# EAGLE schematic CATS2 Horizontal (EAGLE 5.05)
MFG: Bourns; PN: APXE160ARA390ME61G; SOCKET_MFG: Mill-Max Mfg

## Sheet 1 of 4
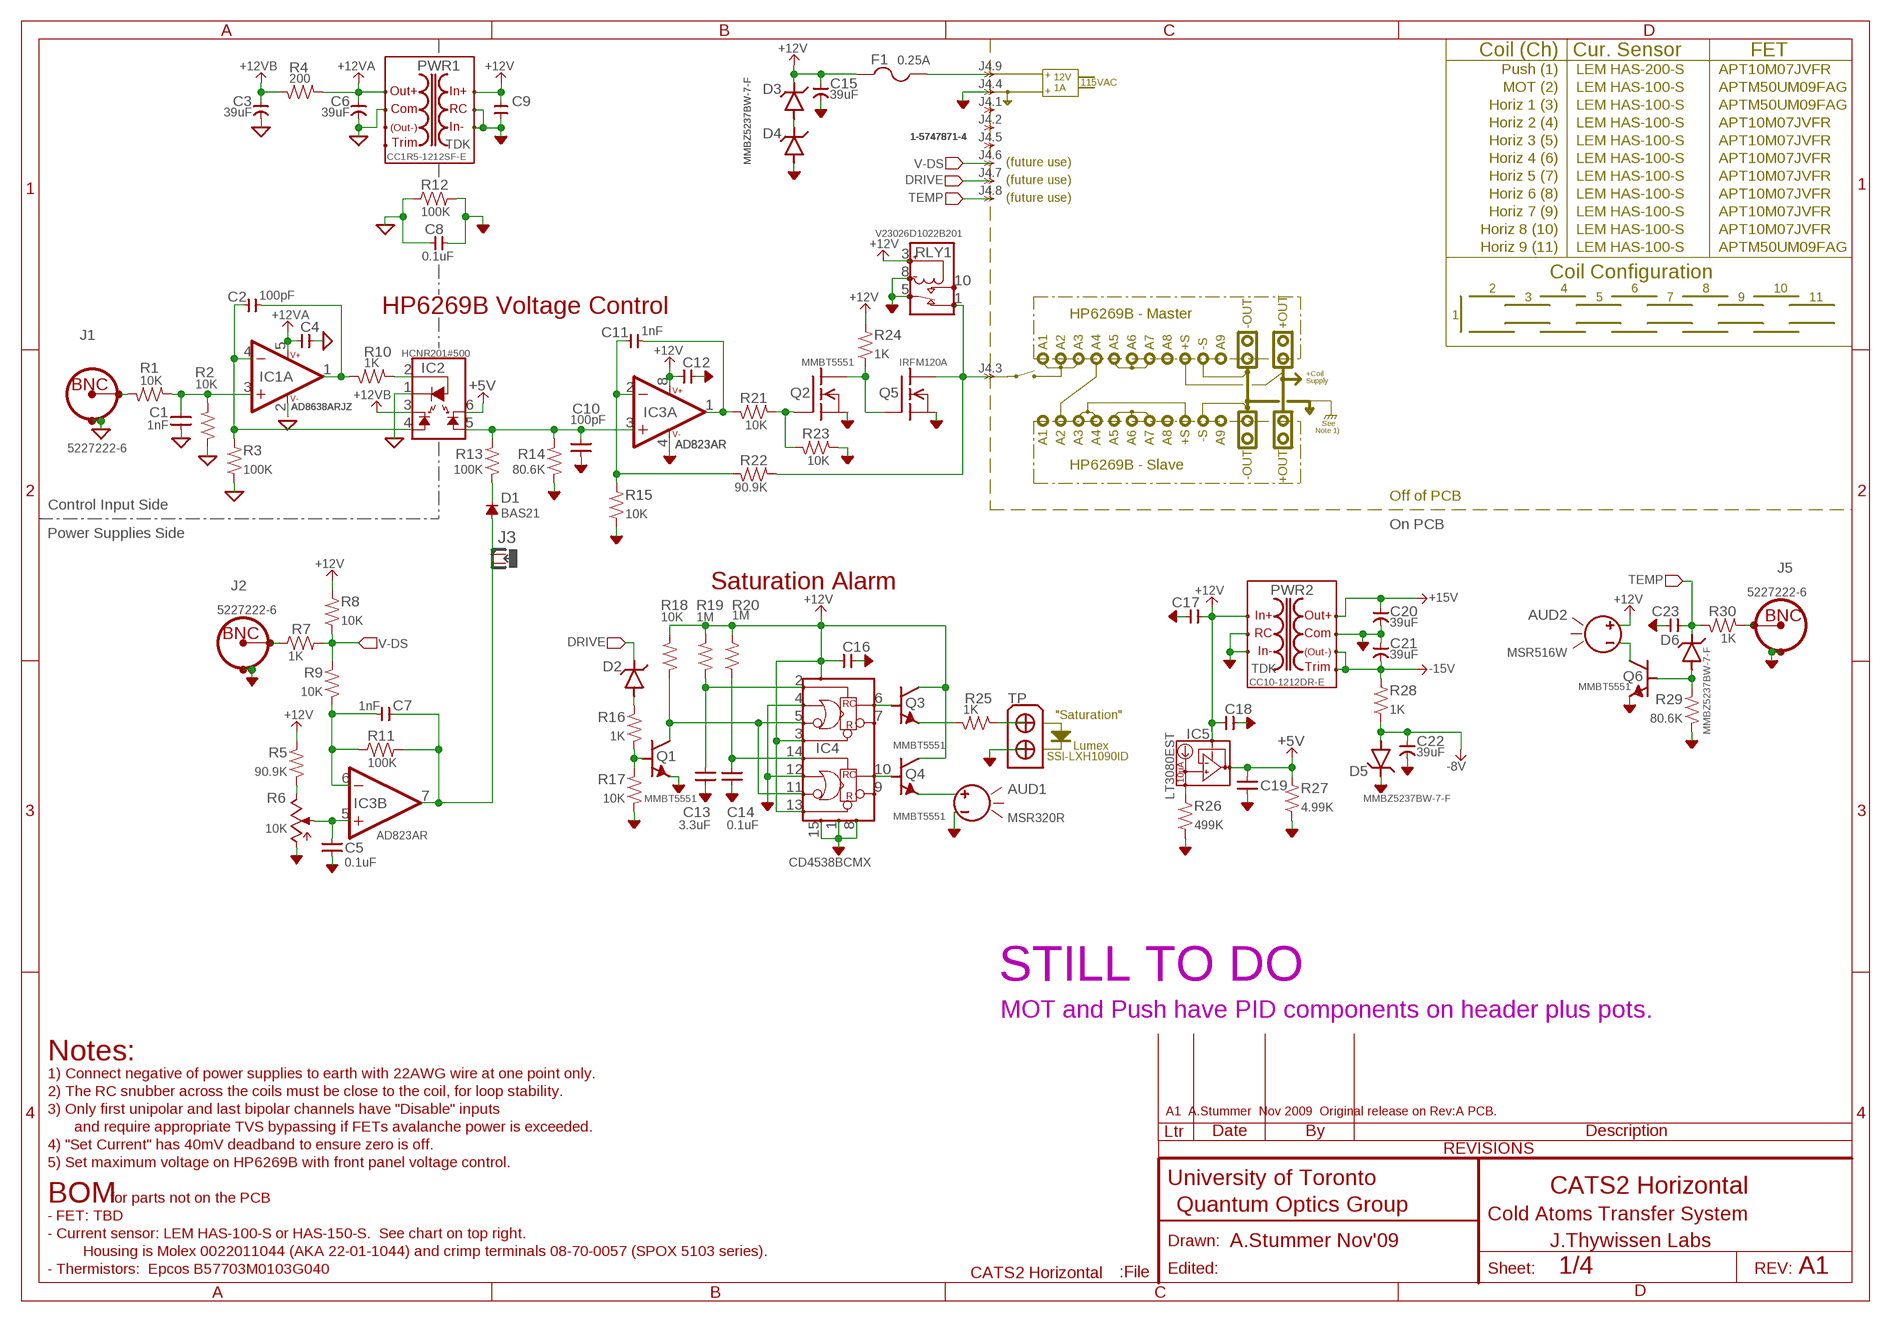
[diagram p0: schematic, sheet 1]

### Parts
AUD1  MSR320R  AUDIO_DEVICE1-MALLORY_MSR  [MALLORY_MSR]
AUD2  MSR516W  AUDIO_DEVICE1-MALLORY_MSR  [MALLORY_MSR]
C1  1nF  CAP-V-0805  [2012(0805)]
C2  100pF  CAP-H-0805  [2012(0805)]
C3  39uF  CAP-POL--NIPPONCHEM_E61  [CAP:NIPPONCHEM_E61]
C4  0.1uF  CAP-H-0805  [2012(0805)]
C5  0.1uF  CAP-V-0805  [2012(0805)]
C6  39uF  CAP-POL--NIPPONCHEM_E61  [CAP:NIPPONCHEM_E61]
C7  1nF  CAP-H-0805  [2012(0805)]
C8  0.1uF  CAP-H-0805  [2012(0805)]
C9  0.1uF  CAP-H-0805  [2012(0805)]
C10  100pF  CAP-V-0805  [2012(0805)]
C11  1nF  CAP-H-0805  [2012(0805)]
C12  0.1uF  CAP-H-0805  [2012(0805)]
C13  3.3uF  CAP-V-0805  [2012(0805)]
C14  0.1uF  CAP-V-0805  [2012(0805)]
C15  39uF  CAP-POL--NIPPONCHEM_E61  [CAP:NIPPONCHEM_E61]
C16  0.1uF  CAP-H-0805  [2012(0805)]
C17  0.1uF  CAP-H-0805  [2012(0805)]
C18  0.1uF  CAP-H-0805  [2012(0805)]
C19  0.1uF  CAP-V-0805  [2012(0805)]
C20  39uF  CAP-POL--NIPPONCHEM_E61  [CAP:NIPPONCHEM_E61]
C21  39uF  CAP-POL--NIPPONCHEM_E61  [CAP:NIPPONCHEM_E61]
C22  39uF  CAP-POL--NIPPONCHEM_E61  [CAP:NIPPONCHEM_E61]
C23  0.1uF  CAP-H-0805  [2012(0805)]
D1  BAS21  DIODE,GENERIC-SOT23  [SOT23]
D2  MMBZ5237BW-7-F  ZENER-SOT23  [SOT23]
D3  MMBZ5237BW-7-F  ZENER-SOT23  [SOT23]
D4  MMBZ5237BW-7-F  ZENER-SOT23  [SOT23]
D5  MMBZ5237BW-7-F  ZENER-SOT23  [SOT23]
D6  MMBZ5237BW-7-F  ZENER-SOT23  [SOT23]
F1  0.25A  FUSE-5X20-4  [FUSE]
IC1  AD8638ARJZ  OPAMP-SOT23-5  [SOT23-5]
IC2  HCNR201#500  OPTO:LINEAR-TYPE1AVAGO#300  [SMD:AVAGO#300(8PIN)]
IC3  AD823AR  OPAMP:AD8___(DUAL)-SOIC-8  [SOIC-8]
IC4  CD4538BCMX  LOGIC,MONOSTABLE,DUAL:MC74HC4538A-SOIC16  [SOIC-16]
IC5  LT3080EST  REGULATOR:LT3080(3PIN,LDO,I-SET)-SOT223  [SOT223(C)]
J1  5227222-6  CONN-BNC-TYPE1VERT  [CONN-BNC-AMP-TYPE1VERT]
J2  5227222-6  CONN-BNC-TYPE1VERT  [CONN-BNC-AMP-TYPE1VERT]
J3  JUMPER-1X2  [JUMPER-1X2]
J4  1-5747871-4  CONN-DB9-TYPE2-AMP_5747XXX  [CONN-DB9-H/V1]
J5  5227222-6  CONN-BNC-TYPE1VERT  [CONN-BNC-AMP-TYPE1VERT]
PWR1  CC1R5-1212SF-E  DC-DC:CCP-__-E(TDK1.5-25W)-CC1R5-R-E  [DC-DC:CC1R5-XXXXX-R-E(TDK/LAMBDA)]
PWR2  CC10-1212DR-E  DC-DC:CCP-__-E(TDK1.5-25W)-CC10-R-E  [DC-DC:CC10-XXXXX-R-E(TDK/LAMBDA)]
Q1  MMBT5551  BJT-NPN-SOT23  [SOT23]
Q2  MMBT5551  MOSFET-N-SOT23(2N7000/2)  [SOT23]
Q3  MMBT5551  BJT-NPN-SOT23  [SOT23]
Q4  MMBT5551  BJT-NPN-SOT23  [SOT23]
Q5  IRFM120A  MOSFET-N-SOT223(C)  [SOT223(C)]
Q6  MMBT5551  BJT-NPN-SOT23  [SOT23]
R1  10K  R-H-0805  [2012(0805)]
R2  10K  R-V-0805  [2012(0805)]
R3  100K  R-V-0805  [2012(0805)]
R4  200  R-H-0805  [2012(0805)]
R5  90.9K  R-V-0805  [2012(0805)]
R6  10K  POT-BOURNS_3361P  [BOURNS_3361P]
R7  1K  R-H-0805  [2012(0805)]
R8  10K  R-V-0805  [2012(0805)]
R9  10K  R-V-0805  [2012(0805)]
R10  1K  R-H-0805  [2012(0805)]
R11  100K  R-H-0805  [2012(0805)]
R12  100K  R-H-0805  [2012(0805)]
R13  100K  R-V-0805  [2012(0805)]
R14  80.6K  R-V-0805  [2012(0805)]
R15  10K  R-V-0805  [2012(0805)]
R16  1K  R-V-0805  [2012(0805)]
R17  10K  R-V-0805  [2012(0805)]
R18  10K  R-V-0805  [2012(0805)]
R19  1M  R-V-0805  [2012(0805)]
R20  1M  R-V-0805  [2012(0805)]
R21  10K  R-H-0805  [2012(0805)]
R22  90.9K  R-H-0805  [2012(0805)]
R23  10K  R-H-0805  [2012(0805)]
R24  1K  R-V-0805  [2012(0805)]
R25  1K  R-H-0805  [2012(0805)]
R26  499K  R-V-0805  [2012(0805)]
R27  4.99K  R-V-0805  [2012(0805)]
R28  1K  R-V-0805  [2012(0805)]
R29  80.6K  R-V-0805  [2012(0805)]
R30  1K  R-H-0805  [2012(0805)]
RLY1  V23026D1022B201  RELAY:SPDT-TYCO_V23026(SMT)  [RELAY:SPDT-TYCO_V23026]
TP  CONN-TP2-1X2  [JUMPER-1X2]

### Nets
+5V: C19.2 IC2.6(VCC2) IC5.2(OUT) R27.2 ; also sheet 2,3,4
+12V [Power]: AUD2.+ C9.1 C12.1 C15.POS C16.1 C17.1 C18.1 D3.3(C) F1.1A IC3.8(PWR:V++) IC4.3(RST1) IC4.13(RST2) IC4.16(VCC) IC5.3(IN) PWR1.+VIN(+IN) PWR2.+VIN(+IN) Q3.3(C) Q4.3(C) R5.2 R8.2 R18.2 R19.2 R20.2 R24.2 RLY1.3(COIL+) ; also sheet 2,3,4
+12VA [Power]: C4.1 C6.POS IC1.5(B:V++) PWR1.+VOUT(+OUT) R4.1 ; also sheet 2,3,4
+12VB: C3.POS IC2.3(VCC1) R4.2 ; also sheet 2,3,4
+15V [Power]: C20.POS PWR2.+VOUT(+OUT) ; also sheet 2,3,4
-8V: C22.POS D5.1(A) R28.1 ; also sheet 2,3,4
-15V [Power]: C21.NEG PWR2.-VOUT(-OUT) PWR2.TRM(TRIM) R28.2 ; also sheet 2,3,4
AGND: AUD1.- C5.1 C8.2 C9.2 C10.1 C12.2 C13.1 C14.1 C15.NEG C16.2 C17.2 C18.2 C19.1 C20.NEG C21.POS C22.NEG C23.2 D4.1(A) D5.3(C) IC3.4(PWR:V-) IC4.1(COM1) IC4.4(A1) IC4.8(COM2) IC4.12(A2) IC4.15(COM3) J2.SHIELD1 J2.SHIELD2 J4.4 J5.SHIELD1 J5.SHIELD2 PWR1.-VIN(-IN) PWR1.RC PWR2.-VIN(-IN) PWR2.COM PWR2.RC Q1.2(E) Q2.2(S) Q5.3(S) Q6.2(E) R6.CCW R12.2 R14.1 R15.1 R17.1 R23.1 R26.1 R27.1 R29.1 RLY1.5(COM) RLY1.8(COIL-) TP.2 ; also sheet 2,3,4
DRIVE: D2.3(C) J4.7 ; also sheet 2,3,4
GND: C1.1 C3.NEG C4.2 C6.NEG C8.1 IC1.2(B:V-) IC2.1(LED-) J1.SHIELD1 J1.SHIELD2 PWR1.COM R2.1 R3.1 R12.1 ; also sheet 2,3,4
N$1: Q2.1(G) R21.1 R23.2
N$2: C11.2 IC3.1(A:OUT) R21.2
N$3: Q2.3(D) Q5.1(G) R24.1
N$4: C11.1 IC3.2(A:-IN) R15.2 R22.2
N$8: J5.CONDUCTOR R30.1
N$9: D3.1(A) D4.3(C)
N$10: D2.1(A) R16.2
N$11: IC4.5(B1) IC4.11(B2) Q1.3(C) R18.1
N$12: IC4.6(Q1) Q3.1(B)
N$13: C14.2 IC4.14(RC2) R20.1
N$14: C13.2 IC4.2(RC1) R19.1
N$15: IC4.10(Q2) Q4.1(B)
N$16: AUD1.+ Q4.2(E)
N$17: R25.1 TP.1
N$18: Q3.2(E) R25.2
N$19: J2.CONDUCTOR R7.1
N$20: J4.3 Q5.2(D) R22.1 RLY1.1(NC)
N$24: Q1.1(B) R16.1 R17.2
N$29: D6.1(A) Q6.1(B) R29.2
N$30: IC5.1(SET) R26.2
N$31 [Power]: F1.2A J4.9
N$41: AUD2.- Q6.3(C)
N$48: D1.1(A) J3.1
N$49: C10.2 IC2.5(I2) IC3.3(A:+IN) R13.2 R14.2
N$50: C2.2 IC1.1(A:OUT) R10.2
N$51: IC2.2(LED+) R10.1
N$52: J1.CONDUCTOR R1.2
N$53: C1.2 IC1.3(A:+IN) R1.1 R2.2
N$54: C2.1 IC1.4(A:-IN) IC2.4(I1) R3.2
N$60: C5.2 IC3.5(B:+IN) R6.W
N$70: R5.1 R6.CW
N$72: C7.1 IC3.7(B:OUT) J3.2 R11.2
N$77: D1.3(C) R13.1
N$78: C7.2 IC3.6(B:-IN) R9.1 R11.1
TEMP: C23.1 D6.3(C) J4.8 R30.2 ; also sheet 2,3,4
V-DS: J4.6 R7.2 R8.1 R9.2 ; also sheet 2,3,4
Unconnected: IC4.7(~Q1) IC4.9(~Q2) J4.1 J4.2 J4.5 PWR1.-VOUT(-OUT) PWR1.TRM(TRIM) RLY1.10(NO)

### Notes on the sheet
- Coil (Ch) | Cur. Sensor | FET
- Push (1) | LEM HAS-200-S | APT10M07JVFR
- + | 12V
- 115VAC
- 1A | MOT (2) | LEM HAS-100-S | APTM50UM09FAG
- +
- Horiz 1 (3) | LEM HAS-100-S | APTM50UM09FAG
- Horiz 2 (4) | LEM HAS-100-S | APT10M07JVFR
- Horiz 3 (5) | LEM HAS-100-S | APT10M07JVFR
- Horiz 4 (6) | LEM HAS-100-S | APT10M07JVFR
- (future use)
- Horiz 5 (7) | LEM HAS-100-S | APT10M07JVFR
- (future use)
- (future use) | Horiz 6 (8) | LEM HAS-100-S | APT10M07JVFR
- Horiz 7 (9) | LEM HAS-100-S | APT10M07JVFR
- Horiz 8 (10) | LEM HAS-100-S | APT10M07JVFR
- Horiz 9 (11) | LEM HAS-100-S | APTM50UM09FAG
- Coil Configuration
- 2 | 4 | 6 | 8 | 10
- 3 | 5 | 7 | 9 | 11
- HP6269B Voltage Control
- HP6269B - Master | 1
- -OUT | +OUT
- A1 | A2 | A3 | A4 | A5 | A6 | A7 | A8 | +S | -S | A9
- +Coil
- Supply
- See
- A1 | A2 | A3 | A4 | A5 | A6 | A7 | A8 | +S | -S | A9
- Note 1)
- -OUT | +OUT
- HP6269B - Slave
- Off of PCB
- Control Input Side
- On PCB
- Power Supplies Side
- Saturation Alarm
- "Saturation"
- Lumex
- SSI-LXH1090ID
- STILL TO DO
- MOT and Push have PID components on header plus pots.
- Notes:
- 1) Connect negative of power supplies to earth with 22AWG wire at one point only.
- 2) The RC snubber across the coils must be close to the coil, for loop stability.
- 3) Only first unipolar and last bipolar channels have "Disable" inputs | A1  A.Stummer  Nov 2009  Original release on Rev:A PCB.
- and require appropriate TVS bypassing if FETs avalanche power is exceeded.
- 4) "Set Current" has 40mV deadband to ensure zero is off.
- 5) Set maximum voltage on HP6269B with front panel voltage control.
- CATS2 Horizontal
- BOM | for parts not on the PCB
- - FET: TBD | Cold Atoms Transfer System
- - Current sensor: LEM HAS-100-S or HAS-150-S.  See chart on top right.
- A.Stummer Nov'09 | J.Thywissen Labs
- Housing is Molex 0022011044 (AKA 22-01-1044) and crimp terminals 08-70-0057 (SPOX 5103 series).
- - Thermistors:  Epcos B57703M0103G040 | A1

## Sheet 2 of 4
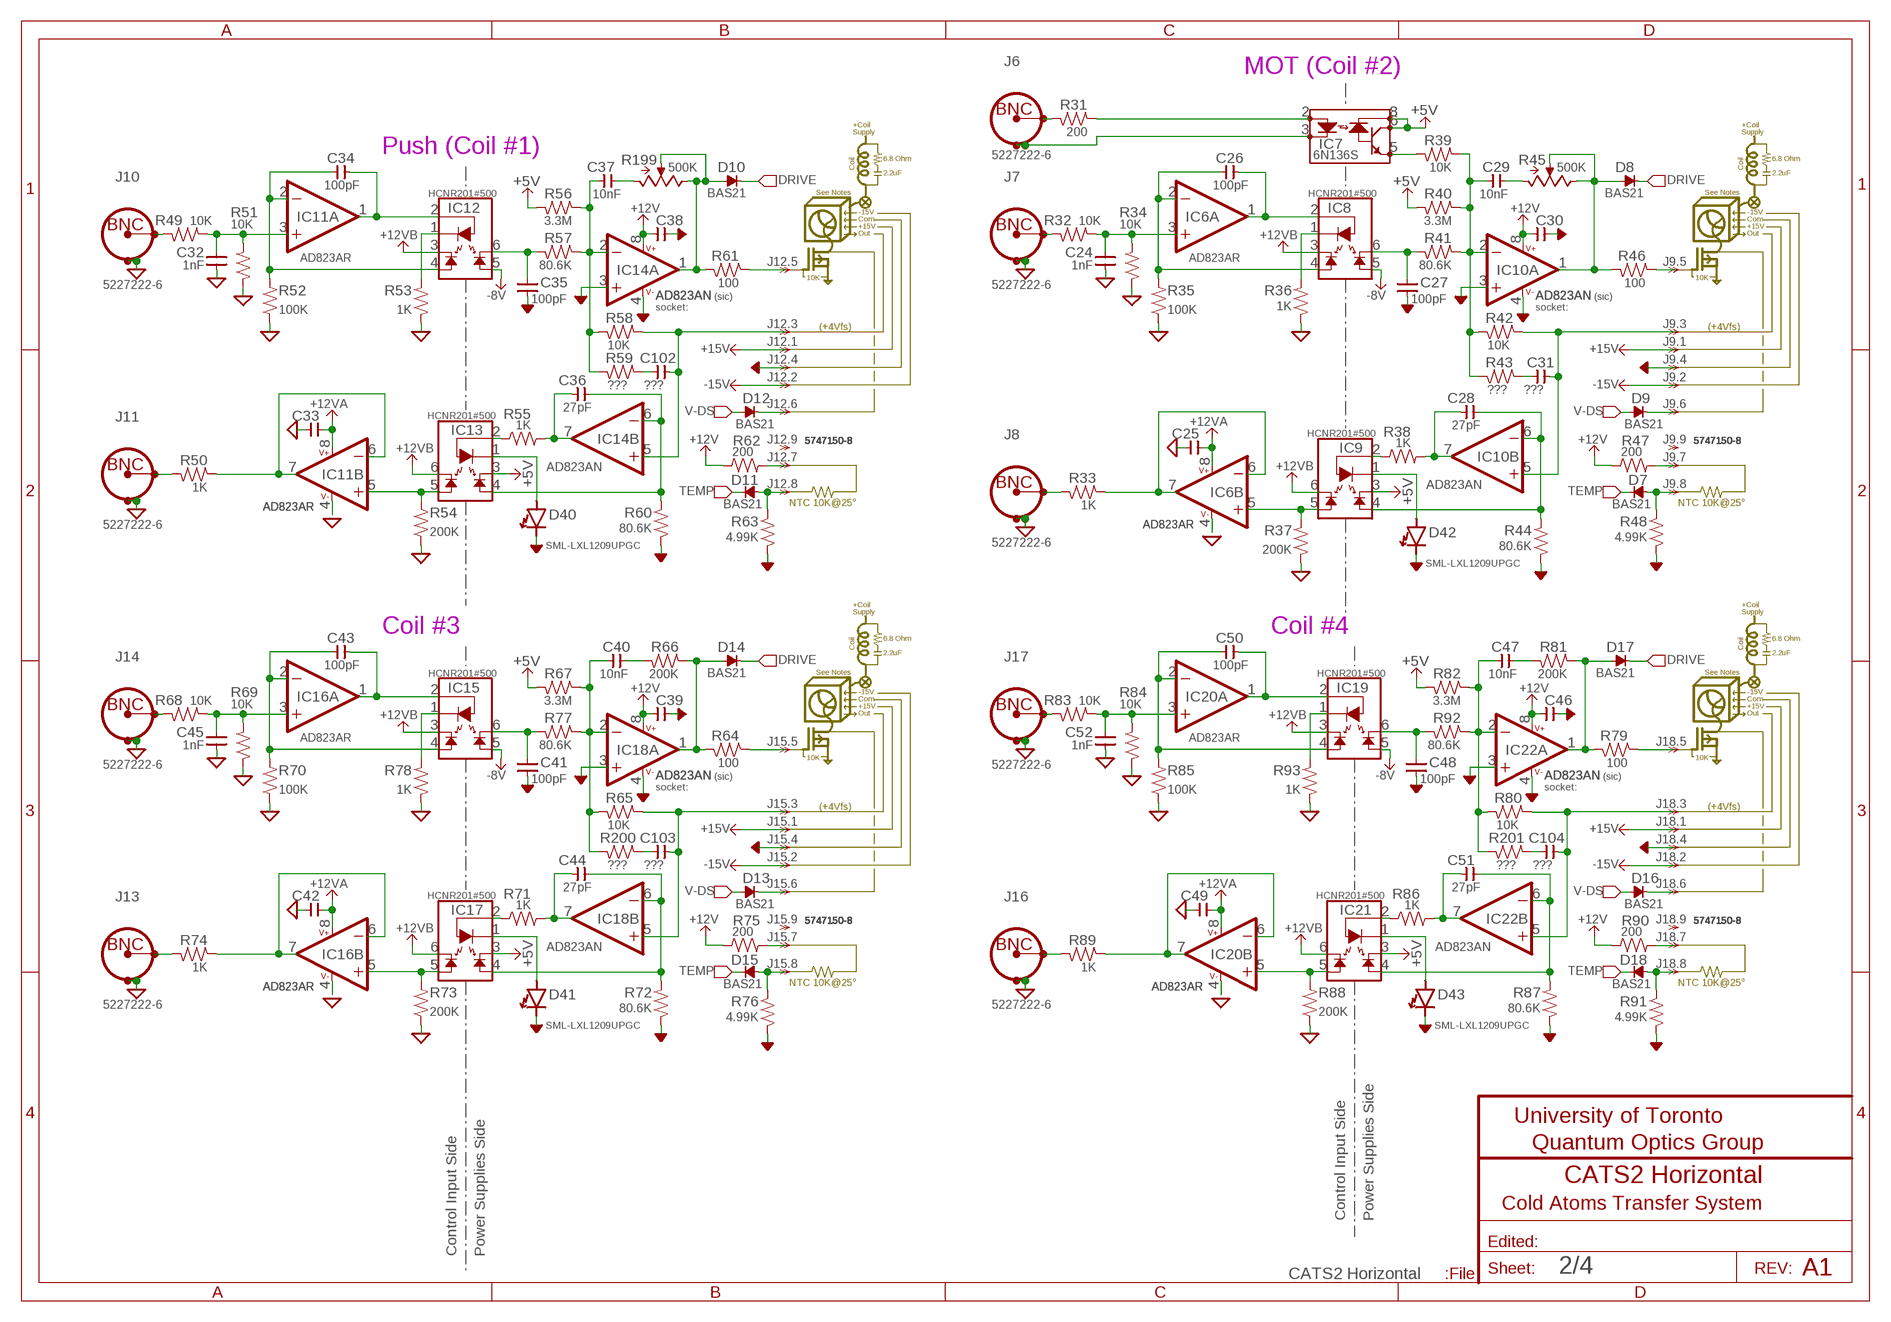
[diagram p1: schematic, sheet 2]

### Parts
C24  1nF  CAP-V-0805  [2012(0805)]
C25  0.1uF  CAP-H-0805  [2012(0805)]
C26  100pF  CAP-H-0805  [2012(0805)]
C27  100pF  CAP-V-0805  [2012(0805)]
C28  27pF  CAP-H-0805  [2012(0805)]
C29  10nF  CAP-H-0805  [2012(0805)]
C30  0.1uF  CAP-H-0805  [2012(0805)]
C31  ???  CAP-H-0805  [2012(0805)]
C32  1nF  CAP-V-0805  [2012(0805)]
C33  0.1uF  CAP-H-0805  [2012(0805)]
C34  100pF  CAP-H-0805  [2012(0805)]
C35  100pF  CAP-V-0805  [2012(0805)]
C36  27pF  CAP-H-0805  [2012(0805)]
C37  10nF  CAP-H-0805  [2012(0805)]
C38  0.1uF  CAP-H-0805  [2012(0805)]
C39  0.1uF  CAP-H-0805  [2012(0805)]
C40  10nF  CAP-H-0805  [2012(0805)]
C41  100pF  CAP-V-0805  [2012(0805)]
C42  0.1uF  CAP-H-0805  [2012(0805)]
C43  100pF  CAP-H-0805  [2012(0805)]
C44  27pF  CAP-H-0805  [2012(0805)]
C45  1nF  CAP-V-0805  [2012(0805)]
C46  0.1uF  CAP-H-0805  [2012(0805)]
C47  10nF  CAP-H-0805  [2012(0805)]
C48  100pF  CAP-V-0805  [2012(0805)]
C49  0.1uF  CAP-H-0805  [2012(0805)]
C50  100pF  CAP-H-0805  [2012(0805)]
C51  27pF  CAP-H-0805  [2012(0805)]
C52  1nF  CAP-V-0805  [2012(0805)]
C102  ???  CAP-H-0805  [2012(0805)]
C103  ???  CAP-H-0805  [2012(0805)]
C104  ???  CAP-H-0805  [2012(0805)]
D7  BAS21  DIODE,GENERIC-SOT23  [SOT23]
D8  BAS21  DIODE,GENERIC-SOT23  [SOT23]
D9  BAS21  DIODE,GENERIC-SOT23  [SOT23]
D10  BAS21  DIODE,GENERIC-SOT23  [SOT23]
D11  BAS21  DIODE,GENERIC-SOT23  [SOT23]
D12  BAS21  DIODE,GENERIC-SOT23  [SOT23]
D13  BAS21  DIODE,GENERIC-SOT23  [SOT23]
D14  BAS21  DIODE,GENERIC-SOT23  [SOT23]
D15  BAS21  DIODE,GENERIC-SOT23  [SOT23]
D16  BAS21  DIODE,GENERIC-SOT23  [SOT23]
D17  BAS21  DIODE,GENERIC-SOT23  [SOT23]
D18  BAS21  DIODE,GENERIC-SOT23  [SOT23]
D40  SML-LXL1209UPGC  LED-1209  [1209]
D41  SML-LXL1209UPGC  LED-1209  [1209]
D42  SML-LXL1209UPGC  LED-1209  [1209]
D43  SML-LXL1209UPGC  LED-1209  [1209]
IC6  AD823AR  OPAMP:AD8___(DUAL)-SOIC-8  [SOIC-8]
IC7  6N136S  OPTO:6N136-S  [SMD:6N13X(8PIN)]
IC8  HCNR201#500  OPTO:LINEAR-TYPE1AVAGO#300  [SMD:AVAGO#300(8PIN)]
IC9  HCNR201#500  OPTO:LINEAR-TYPE1AVAGO#300  [SMD:AVAGO#300(8PIN)]
IC10  AD823AN  OPAMP:AD8___(DUAL)-DIP8  [DIL08]
IC11  AD823AR  OPAMP:AD8___(DUAL)-SOIC-8  [SOIC-8]
IC12  HCNR201#500  OPTO:LINEAR-TYPE1AVAGO#300  [SMD:AVAGO#300(8PIN)]
IC13  HCNR201#500  OPTO:LINEAR-TYPE1AVAGO#300  [SMD:AVAGO#300(8PIN)]
IC14  AD823AN  OPAMP:AD8___(DUAL)-DIP8  [DIL08]
IC15  HCNR201#500  OPTO:LINEAR-TYPE1AVAGO#300  [SMD:AVAGO#300(8PIN)]
IC16  AD823AR  OPAMP:AD8___(DUAL)-SOIC-8  [SOIC-8]
IC17  HCNR201#500  OPTO:LINEAR-TYPE1AVAGO#300  [SMD:AVAGO#300(8PIN)]
IC18  AD823AN  OPAMP:AD8___(DUAL)-DIP8  [DIL08]
IC19  HCNR201#500  OPTO:LINEAR-TYPE1AVAGO#300  [SMD:AVAGO#300(8PIN)]
IC20  AD823AR  OPAMP:AD8___(DUAL)-SOIC-8  [SOIC-8]
IC21  HCNR201#500  OPTO:LINEAR-TYPE1AVAGO#300  [SMD:AVAGO#300(8PIN)]
IC22  AD823AN  OPAMP:AD8___(DUAL)-DIP8  [DIL08]
J6  5227222-6  CONN-BNC-TYPE1VERT  [CONN-BNC-AMP-TYPE1VERT]
J7  5227222-6  CONN-BNC-TYPE1VERT  [CONN-BNC-AMP-TYPE1VERT]
J8  5227222-6  CONN-BNC-TYPE1VERT  [CONN-BNC-AMP-TYPE1VERT]
J9  5747150-8  CONN-DB9-TYPE2-AMP_5747XXX  [CONN-DB9-H/V1]
J10  5227222-6  CONN-BNC-TYPE1VERT  [CONN-BNC-AMP-TYPE1VERT]
J11  5227222-6  CONN-BNC-TYPE1VERT  [CONN-BNC-AMP-TYPE1VERT]
J12  5747150-8  CONN-DB9-TYPE2-AMP_5747XXX  [CONN-DB9-H/V1]
J13  5227222-6  CONN-BNC-TYPE1VERT  [CONN-BNC-AMP-TYPE1VERT]
J14  5227222-6  CONN-BNC-TYPE1VERT  [CONN-BNC-AMP-TYPE1VERT]
J15  5747150-8  CONN-DB9-TYPE2-AMP_5747XXX  [CONN-DB9-H/V1]
J16  5227222-6  CONN-BNC-TYPE1VERT  [CONN-BNC-AMP-TYPE1VERT]
J17  5227222-6  CONN-BNC-TYPE1VERT  [CONN-BNC-AMP-TYPE1VERT]
J18  5747150-8  CONN-DB9-TYPE2-AMP_5747XXX  [CONN-DB9-H/V1]
R31  200  R-H-0805  [2012(0805)]
R32  10K  R-H-0805  [2012(0805)]
R33  1K  R-H-0805  [2012(0805)]
R34  10K  R-V-0805  [2012(0805)]
R35  100K  R-V-0805  [2012(0805)]
R36  1K  R-V-0805  [2012(0805)]
R37  200K  R-V-0805  [2012(0805)]
R38  1K  R-H-0805  [2012(0805)]
R39  10K  R-H-0805  [2012(0805)]
R40  3.3M  R-H-0805  [2012(0805)]
R41  80.6K  R-H-0805  [2012(0805)]
R42  10K  R-H-0805  [2012(0805)]
R43  ???  R-H-0805  [2012(0805)]
R44  80.6K  R-V-0805  [2012(0805)]
R45  500K  POT-BOURNS_3361P  [BOURNS_3361P]
R46  100  R-H-0805  [2012(0805)]
R47  200  R-H-0805  [2012(0805)]
R48  4.99K  R-V-0805  [2012(0805)]
R49  10K  R-H-0805  [2012(0805)]
R50  1K  R-H-0805  [2012(0805)]
R51  10K  R-V-0805  [2012(0805)]
R52  100K  R-V-0805  [2012(0805)]
R53  1K  R-V-0805  [2012(0805)]
R54  200K  R-V-0805  [2012(0805)]
R55  1K  R-H-0805  [2012(0805)]
R56  3.3M  R-H-0805  [2012(0805)]
R57  80.6K  R-H-0805  [2012(0805)]
R58  10K  R-H-0805  [2012(0805)]
R59  ???  R-H-0805  [2012(0805)]
R60  80.6K  R-V-0805  [2012(0805)]
R61  100  R-H-0805  [2012(0805)]
R62  200  R-H-0805  [2012(0805)]
R63  4.99K  R-V-0805  [2012(0805)]
R64  100  R-H-0805  [2012(0805)]
R65  10K  R-H-0805  [2012(0805)]
R66  200K  R-H-0805  [2012(0805)]
R67  3.3M  R-H-0805  [2012(0805)]
R68  10K  R-H-0805  [2012(0805)]
R69  10K  R-V-0805  [2012(0805)]
R70  100K  R-V-0805  [2012(0805)]
R71  1K  R-H-0805  [2012(0805)]
R72  80.6K  R-V-0805  [2012(0805)]
R73  200K  R-V-0805  [2012(0805)]
R74  1K  R-H-0805  [2012(0805)]
R75  200  R-H-0805  [2012(0805)]
R76  4.99K  R-V-0805  [2012(0805)]
R77  80.6K  R-H-0805  [2012(0805)]
R78  1K  R-V-0805  [2012(0805)]
R79  100  R-H-0805  [2012(0805)]
R80  10K  R-H-0805  [2012(0805)]
R81  200K  R-H-0805  [2012(0805)]
R82  3.3M  R-H-0805  [2012(0805)]
R83  10K  R-H-0805  [2012(0805)]
R84  10K  R-V-0805  [2012(0805)]
R85  100K  R-V-0805  [2012(0805)]
R86  1K  R-H-0805  [2012(0805)]
R87  80.6K  R-V-0805  [2012(0805)]
R88  200K  R-V-0805  [2012(0805)]
R89  1K  R-H-0805  [2012(0805)]
R90  200  R-H-0805  [2012(0805)]
R91  4.99K  R-V-0805  [2012(0805)]
R92  80.6K  R-H-0805  [2012(0805)]
R93  1K  R-V-0805  [2012(0805)]
R199  500K  POT-BOURNS_3361P  [BOURNS_3361P]
R200  ???  R-H-0805  [2012(0805)]
R201  ???  R-H-0805  [2012(0805)]

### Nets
+5V: IC7.6(OUT) IC7.8(VDD) IC9.3(VCC1) IC13.3(VCC1) IC17.3(VCC1) IC21.3(VCC1) R40.2 R56.2 R67.2 R82.2 ; also sheet 1,3,4
+12V [Power]: C30.1 C38.1 C39.1 C46.1 IC10.8(PWR:V++) IC14.8(PWR:V++) IC18.8(PWR:V++) IC22.8(PWR:V++) R47.1 R62.1 R75.1 R90.1 ; also sheet 1,3,4
+12VA [Power]: C25.1 C33.1 C42.1 C49.1 IC6.8(PWR:V++) IC11.8(PWR:V++) IC16.8(PWR:V++) IC20.8(PWR:V++) ; also sheet 1,3,4
+12VB: IC8.3(VCC1) IC9.6(VCC2) IC12.3(VCC1) IC13.6(VCC2) IC15.3(VCC1) IC17.6(VCC2) IC19.3(VCC1) IC21.6(VCC2) ; also sheet 1,3,4
+15V [Power]: J9.1 J12.1 J15.1 J18.1 ; also sheet 1,3,4
-8V: IC8.5(I2) IC12.5(I2) IC15.5(I2) IC19.5(I2) ; also sheet 1,3,4
-15V [Power]: J9.2 J12.2 J15.2 J18.2 ; also sheet 1,3,4
AGND: C27.1 C30.2 C35.1 C38.2 C39.2 C41.1 C46.2 C48.1 D40.K(C) D41.K(C) D42.K(C) D43.K(C) IC10.3(A:+IN) IC10.4(PWR:V-) IC14.3(A:+IN) IC14.4(PWR:V-) IC18.3(A:+IN) IC18.4(PWR:V-) IC22.3(A:+IN) IC22.4(PWR:V-) J9.4 J12.4 J15.4 J18.4 R44.1 R48.1 R60.1 R63.1 R72.1 R76.1 R87.1 R91.1 ; also sheet 1,3,4
DRIVE: D8.3(C) D10.3(C) D14.3(C) D17.3(C) ; also sheet 1,3,4
GND: C24.1 C25.2 C32.1 C33.2 C42.2 C45.1 C49.2 C52.1 IC6.4(PWR:V-) IC11.4(PWR:V-) IC16.4(PWR:V-) IC20.4(PWR:V-) J7.SHIELD1 J7.SHIELD2 J8.SHIELD1 J8.SHIELD2 J10.SHIELD1 J10.SHIELD2 J11.SHIELD1 J11.SHIELD2 J13.SHIELD1 J13.SHIELD2 J14.SHIELD1 J14.SHIELD2 J16.SHIELD1 J16.SHIELD2 J17.SHIELD1 J17.SHIELD2 R34.1 R35.1 R36.1 R37.1 R51.1 R52.1 R53.1 R54.1 R69.1 R70.1 R73.1 R78.1 R84.1 R85.1 R88.1 R93.1 ; also sheet 1,3,4
N$5: D9.3(C) J9.6
N$6: J9.7 R47.2
N$7: D7.1(A) J9.8 R48.2
N$21: J12.5 R61.1
N$22: C27.2 IC8.6(VCC2) R41.2
N$23: D10.1(A) IC14.1(A:OUT) R61.2 R199.CW R199.W
N$25: C37.1 IC14.2(A:-IN) R56.1 R57.1 R58.2 R59.2
N$26: C102.2 IC14.5(B:+IN) J12.3 R58.1
N$27: C37.2 R199.CCW
N$28: C34.2 IC11.1(A:OUT) IC12.2(LED+)
N$32: J15.5 R64.1
N$33: J10.CONDUCTOR R49.2
N$34: C32.2 IC11.3(A:+IN) R49.1 R51.2
N$35: C34.1 IC11.2(A:-IN) IC12.4(I1) R52.2
N$36: C36.2 IC14.7(B:OUT) R55.2
N$37: IC13.2(LED+) R55.1
N$38: C36.1 IC13.4(I1) IC14.6(B:-IN) R60.2
N$39: IC11.5(B:+IN) IC13.5(I2) R54.2
N$40: IC11.6(B:-IN) IC11.7(B:OUT) R50.1
N$42: J11.CONDUCTOR R50.2
N$43: J9.5 R46.1
N$44: D8.1(A) IC10.1(A:OUT) R45.CW R45.W R46.2
N$45: C29.1 IC10.2(A:-IN) R39.1 R40.1 R41.1 R42.2 R43.2
N$46: C31.2 IC10.5(B:+IN) J9.3 R42.1
N$47: C29.2 R45.CCW
N$55: C26.2 IC6.1(A:OUT) IC8.2(LED+)
N$56: C31.1 R43.1
N$57: J7.CONDUCTOR R32.2
N$58: C24.2 IC6.3(A:+IN) R32.1 R34.2
N$59: C26.1 IC6.2(A:-IN) IC8.4(I1) R35.2
N$61: C28.2 IC10.7(B:OUT) R38.2
N$62: IC9.2(LED+) R38.1
N$63: C28.1 IC9.4(I1) IC10.6(B:-IN) R44.2
N$64: IC6.5(B:+IN) IC9.5(I2) R37.2
N$65: IC6.6(B:-IN) IC6.7(B:OUT) R33.1
N$66: J8.CONDUCTOR R33.2
N$67: J6.CONDUCTOR R31.2
N$68: IC7.2(ANODE) R31.1
N$69: IC7.3(CATHODE) J6.SHIELD1 J6.SHIELD2
N$71: IC7.5(COM) R39.2
N$73: D12.3(C) J12.6
N$74: J12.7 R62.2
N$75: D11.1(A) J12.8 R63.2
N$76: C35.2 IC12.6(VCC2) R57.2
N$79: IC8.1(LED-) R36.2
N$80: IC12.1(LED-) R53.2
N$81: D14.1(A) IC18.1(A:OUT) R64.2 R66.1
N$82: C40.1 IC18.2(A:-IN) R65.2 R67.1 R77.1 R200.2
N$83: C103.2 IC18.5(B:+IN) J15.3 R65.1
N$84: C40.2 R66.2
N$85: C43.2 IC15.2(LED+) IC16.1(A:OUT)
N$86: J14.CONDUCTOR R68.2
N$87: C45.2 IC16.3(A:+IN) R68.1 R69.2
N$88: C43.1 IC15.4(I1) IC16.2(A:-IN) R70.2
N$89: C44.2 IC18.7(B:OUT) R71.2
N$90: IC17.2(LED+) R71.1
N$91: C44.1 IC17.4(I1) IC18.6(B:-IN) R72.2
N$92: IC16.5(B:+IN) IC17.5(I2) R73.2
N$93: IC16.6(B:-IN) IC16.7(B:OUT) R74.1
N$94: J13.CONDUCTOR R74.2
N$95: D13.3(C) J15.6
N$96: J15.7 R75.2
N$97: D15.1(A) J15.8 R76.2
N$98: C41.2 IC15.6(VCC2) R77.2
N$99: IC15.1(LED-) R78.2
N$100: J18.5 R79.1
N$101: D17.1(A) IC22.1(A:OUT) R79.2 R81.1
N$102: C47.1 IC22.2(A:-IN) R80.2 R82.1 R92.1 R201.2
N$103: C104.2 IC22.5(B:+IN) J18.3 R80.1
N$104: C47.2 R81.2
N$105: C50.2 IC19.2(LED+) IC20.1(A:OUT)
N$106: J17.CONDUCTOR R83.2
N$107: C52.2 IC20.3(A:+IN) R83.1 R84.2
N$108: C50.1 IC19.4(I1) IC20.2(A:-IN) R85.2
N$109: C51.2 IC22.7(B:OUT) R86.2
N$110: IC21.2(LED+) R86.1
N$111: C51.1 IC21.4(I1) IC22.6(B:-IN) R87.2
N$112: IC20.5(B:+IN) IC21.5(I2) R88.2
N$113: IC20.6(B:-IN) IC20.7(B:OUT) R89.1
N$114: J16.CONDUCTOR R89.2
N$115: D16.3(C) J18.6
N$116: J18.7 R90.2
N$117: D18.1(A) J18.8 R91.2
N$118: C48.2 IC19.6(VCC2) R92.2
N$119: IC19.1(LED-) R93.2
N$260: C102.1 R59.1
N$261: C103.1 R200.1
N$262: C104.1 R201.1
N$267: D40.A IC13.1(LED-)
N$271: D41.A IC17.1(LED-)
N$272: D42.A IC9.1(LED-)
N$273: D43.A IC21.1(LED-)
TEMP: D7.3(C) D11.3(C) D15.3(C) D18.3(C) ; also sheet 1,3,4
V-DS: D9.1(A) D12.1(A) D13.1(A) D16.1(A) ; also sheet 1,3,4
Unconnected: J9.9 J12.9 J15.9 J18.9

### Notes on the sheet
- MOT (Coil #2)
- +Coil | +Coil
- Supply | Supply
- Push (Coil #1)
- 6.8 Ohm | 6.8 Ohm
- Coil | Coil
- 2.2uF | 2.2uF
- See Notes | See Notes
- -15V | -15V
- Com | Com
- +15V | +15V
- Out | Out
- 10K | 10K
- (sic) | (sic)
- socket: | socket:
- (+4Vfs) | (+4Vfs)
- NTC 10K@25° | NTC 10K@25°
- +Coil | +Coil
- Supply | Supply
- Coil #3 | Coil #4
- 6.8 Ohm | 6.8 Ohm
- Coil | Coil
- 2.2uF | 2.2uF
- See Notes | See Notes
- -15V | -15V
- Com | Com
- +15V | +15V
- Out | Out
- 10K | 10K
- (sic) | (sic)
- socket: | socket:
- (+4Vfs) | (+4Vfs)
- NTC 10K@25° | NTC 10K@25°
- CATS2 Horizontal
- Cold Atoms Transfer System
- Control Input Side | Power Supplies Side
- Control Input Side | Power Supplies Side
- A1

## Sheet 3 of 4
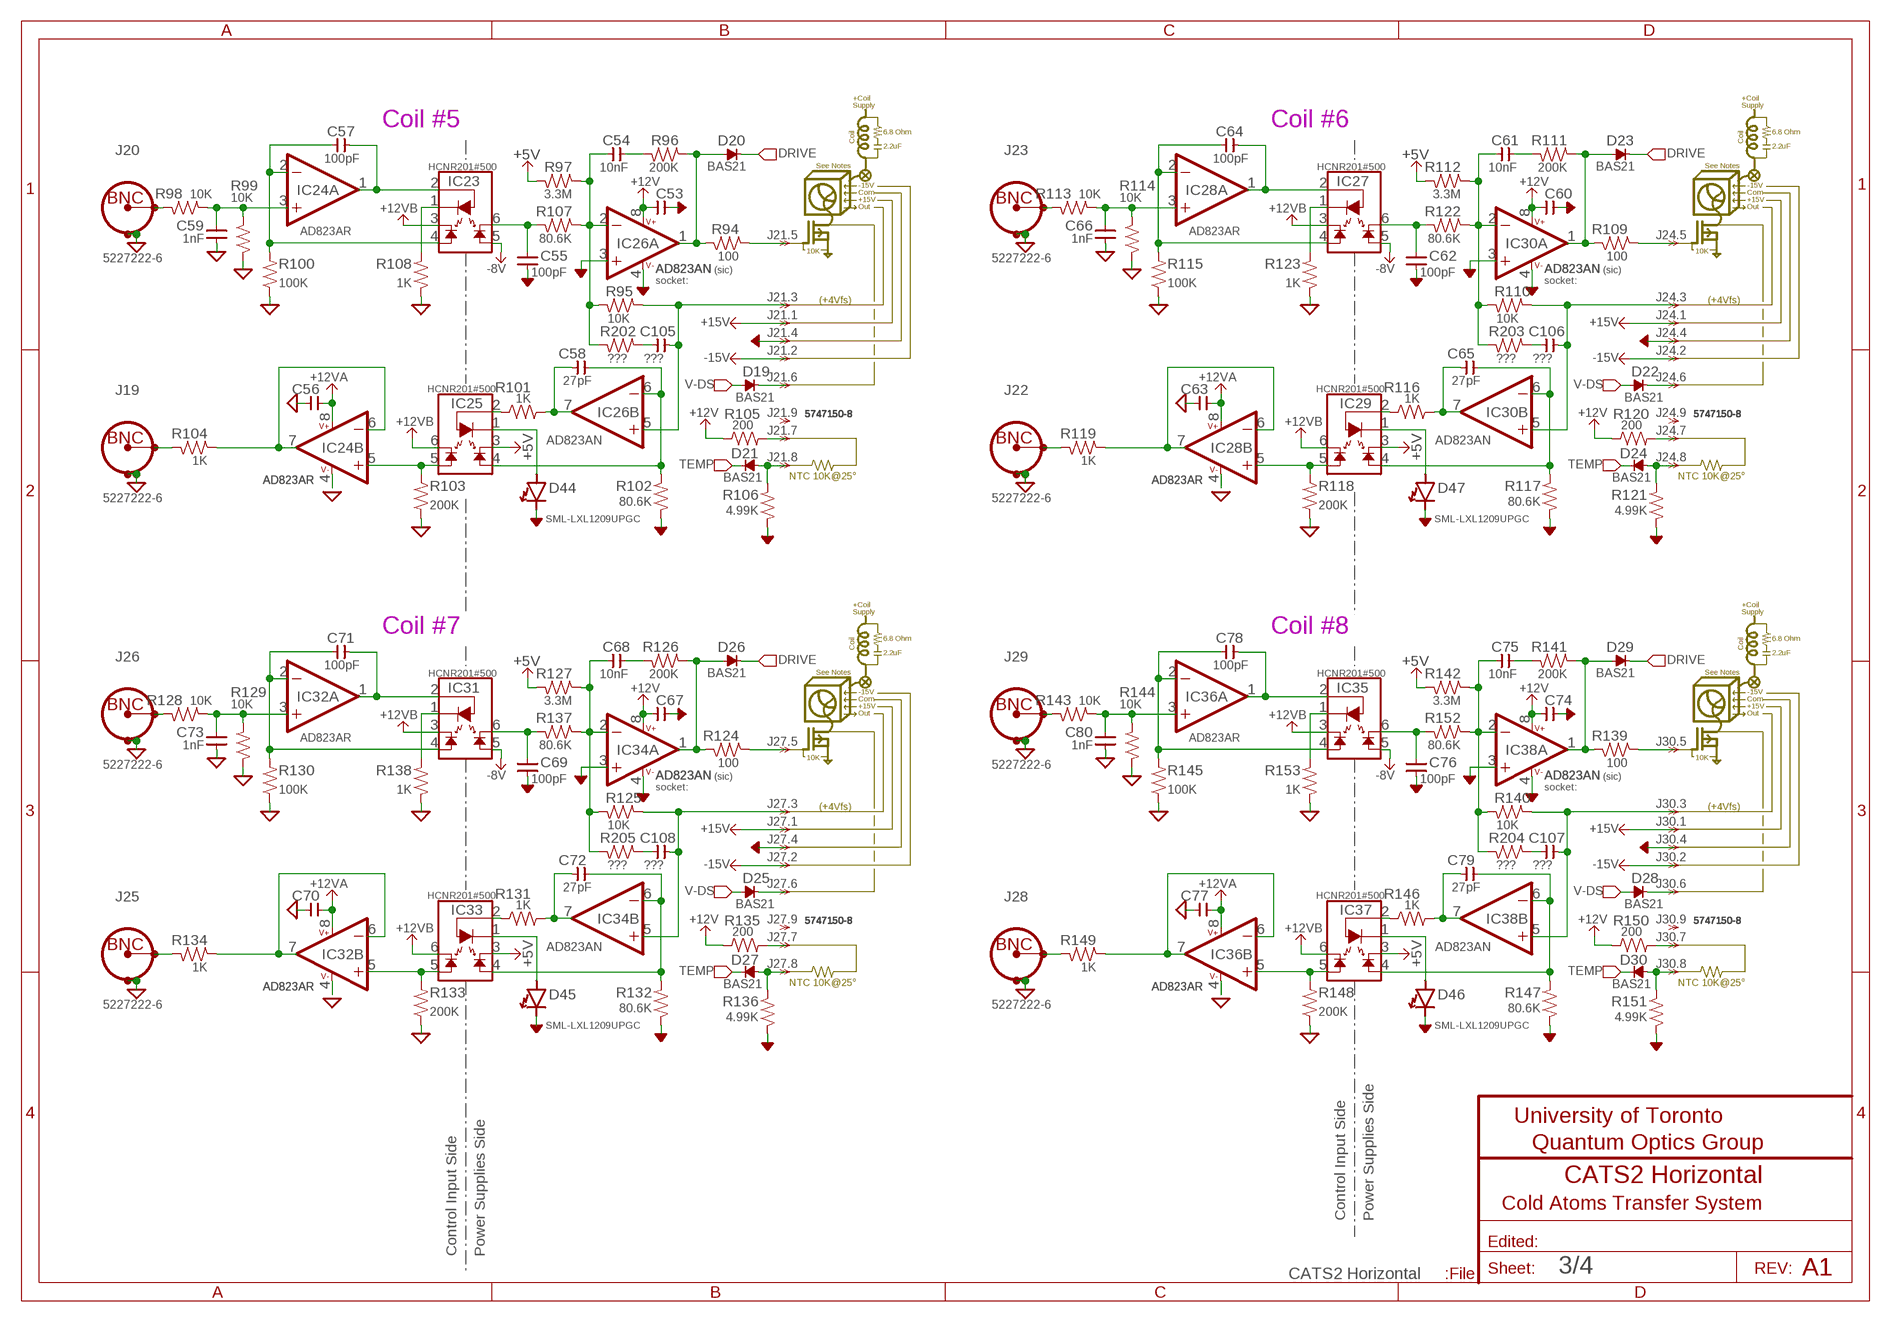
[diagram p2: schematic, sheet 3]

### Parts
C53  0.1uF  CAP-H-0805  [2012(0805)]
C54  10nF  CAP-H-0805  [2012(0805)]
C55  100pF  CAP-V-0805  [2012(0805)]
C56  0.1uF  CAP-H-0805  [2012(0805)]
C57  100pF  CAP-H-0805  [2012(0805)]
C58  27pF  CAP-H-0805  [2012(0805)]
C59  1nF  CAP-V-0805  [2012(0805)]
C60  0.1uF  CAP-H-0805  [2012(0805)]
C61  10nF  CAP-H-0805  [2012(0805)]
C62  100pF  CAP-V-0805  [2012(0805)]
C63  0.1uF  CAP-H-0805  [2012(0805)]
C64  100pF  CAP-H-0805  [2012(0805)]
C65  27pF  CAP-H-0805  [2012(0805)]
C66  1nF  CAP-V-0805  [2012(0805)]
C67  0.1uF  CAP-H-0805  [2012(0805)]
C68  10nF  CAP-H-0805  [2012(0805)]
C69  100pF  CAP-V-0805  [2012(0805)]
C70  0.1uF  CAP-H-0805  [2012(0805)]
C71  100pF  CAP-H-0805  [2012(0805)]
C72  27pF  CAP-H-0805  [2012(0805)]
C73  1nF  CAP-V-0805  [2012(0805)]
C74  0.1uF  CAP-H-0805  [2012(0805)]
C75  10nF  CAP-H-0805  [2012(0805)]
C76  100pF  CAP-V-0805  [2012(0805)]
C77  0.1uF  CAP-H-0805  [2012(0805)]
C78  100pF  CAP-H-0805  [2012(0805)]
C79  27pF  CAP-H-0805  [2012(0805)]
C80  1nF  CAP-V-0805  [2012(0805)]
C105  ???  CAP-H-0805  [2012(0805)]
C106  ???  CAP-H-0805  [2012(0805)]
C107  ???  CAP-H-0805  [2012(0805)]
C108  ???  CAP-H-0805  [2012(0805)]
D19  BAS21  DIODE,GENERIC-SOT23  [SOT23]
D20  BAS21  DIODE,GENERIC-SOT23  [SOT23]
D21  BAS21  DIODE,GENERIC-SOT23  [SOT23]
D22  BAS21  DIODE,GENERIC-SOT23  [SOT23]
D23  BAS21  DIODE,GENERIC-SOT23  [SOT23]
D24  BAS21  DIODE,GENERIC-SOT23  [SOT23]
D25  BAS21  DIODE,GENERIC-SOT23  [SOT23]
D26  BAS21  DIODE,GENERIC-SOT23  [SOT23]
D27  BAS21  DIODE,GENERIC-SOT23  [SOT23]
D28  BAS21  DIODE,GENERIC-SOT23  [SOT23]
D29  BAS21  DIODE,GENERIC-SOT23  [SOT23]
D30  BAS21  DIODE,GENERIC-SOT23  [SOT23]
D44  SML-LXL1209UPGC  LED-1209  [1209]
D45  SML-LXL1209UPGC  LED-1209  [1209]
D46  SML-LXL1209UPGC  LED-1209  [1209]
D47  SML-LXL1209UPGC  LED-1209  [1209]
IC23  HCNR201#500  OPTO:LINEAR-TYPE1AVAGO#300  [SMD:AVAGO#300(8PIN)]
IC24  AD823AR  OPAMP:AD8___(DUAL)-SOIC-8  [SOIC-8]
IC25  HCNR201#500  OPTO:LINEAR-TYPE1AVAGO#300  [SMD:AVAGO#300(8PIN)]
IC26  AD823AN  OPAMP:AD8___(DUAL)-DIP8  [DIL08]
IC27  HCNR201#500  OPTO:LINEAR-TYPE1AVAGO#300  [SMD:AVAGO#300(8PIN)]
IC28  AD823AR  OPAMP:AD8___(DUAL)-SOIC-8  [SOIC-8]
IC29  HCNR201#500  OPTO:LINEAR-TYPE1AVAGO#300  [SMD:AVAGO#300(8PIN)]
IC30  AD823AN  OPAMP:AD8___(DUAL)-DIP8  [DIL08]
IC31  HCNR201#500  OPTO:LINEAR-TYPE1AVAGO#300  [SMD:AVAGO#300(8PIN)]
IC32  AD823AR  OPAMP:AD8___(DUAL)-SOIC-8  [SOIC-8]
IC33  HCNR201#500  OPTO:LINEAR-TYPE1AVAGO#300  [SMD:AVAGO#300(8PIN)]
IC34  AD823AN  OPAMP:AD8___(DUAL)-DIP8  [DIL08]
IC35  HCNR201#500  OPTO:LINEAR-TYPE1AVAGO#300  [SMD:AVAGO#300(8PIN)]
IC36  AD823AR  OPAMP:AD8___(DUAL)-SOIC-8  [SOIC-8]
IC37  HCNR201#500  OPTO:LINEAR-TYPE1AVAGO#300  [SMD:AVAGO#300(8PIN)]
IC38  AD823AN  OPAMP:AD8___(DUAL)-DIP8  [DIL08]
J19  5227222-6  CONN-BNC-TYPE1VERT  [CONN-BNC-AMP-TYPE1VERT]
J20  5227222-6  CONN-BNC-TYPE1VERT  [CONN-BNC-AMP-TYPE1VERT]
J21  5747150-8  CONN-DB9-TYPE2-AMP_5747XXX  [CONN-DB9-H/V1]
J22  5227222-6  CONN-BNC-TYPE1VERT  [CONN-BNC-AMP-TYPE1VERT]
J23  5227222-6  CONN-BNC-TYPE1VERT  [CONN-BNC-AMP-TYPE1VERT]
J24  5747150-8  CONN-DB9-TYPE2-AMP_5747XXX  [CONN-DB9-H/V1]
J25  5227222-6  CONN-BNC-TYPE1VERT  [CONN-BNC-AMP-TYPE1VERT]
J26  5227222-6  CONN-BNC-TYPE1VERT  [CONN-BNC-AMP-TYPE1VERT]
J27  5747150-8  CONN-DB9-TYPE2-AMP_5747XXX  [CONN-DB9-H/V1]
J28  5227222-6  CONN-BNC-TYPE1VERT  [CONN-BNC-AMP-TYPE1VERT]
J29  5227222-6  CONN-BNC-TYPE1VERT  [CONN-BNC-AMP-TYPE1VERT]
J30  5747150-8  CONN-DB9-TYPE2-AMP_5747XXX  [CONN-DB9-H/V1]
R94  100  R-H-0805  [2012(0805)]
R95  10K  R-H-0805  [2012(0805)]
R96  200K  R-H-0805  [2012(0805)]
R97  3.3M  R-H-0805  [2012(0805)]
R98  10K  R-H-0805  [2012(0805)]
R99  10K  R-V-0805  [2012(0805)]
R100  100K  R-V-0805  [2012(0805)]
R101  1K  R-H-0805  [2012(0805)]
R102  80.6K  R-V-0805  [2012(0805)]
R103  200K  R-V-0805  [2012(0805)]
R104  1K  R-H-0805  [2012(0805)]
R105  200  R-H-0805  [2012(0805)]
R106  4.99K  R-V-0805  [2012(0805)]
R107  80.6K  R-H-0805  [2012(0805)]
R108  1K  R-V-0805  [2012(0805)]
R109  100  R-H-0805  [2012(0805)]
R110  10K  R-H-0805  [2012(0805)]
R111  200K  R-H-0805  [2012(0805)]
R112  3.3M  R-H-0805  [2012(0805)]
R113  10K  R-H-0805  [2012(0805)]
R114  10K  R-V-0805  [2012(0805)]
R115  100K  R-V-0805  [2012(0805)]
R116  1K  R-H-0805  [2012(0805)]
R117  80.6K  R-V-0805  [2012(0805)]
R118  200K  R-V-0805  [2012(0805)]
R119  1K  R-H-0805  [2012(0805)]
R120  200  R-H-0805  [2012(0805)]
R121  4.99K  R-V-0805  [2012(0805)]
R122  80.6K  R-H-0805  [2012(0805)]
R123  1K  R-V-0805  [2012(0805)]
R124  100  R-H-0805  [2012(0805)]
R125  10K  R-H-0805  [2012(0805)]
R126  200K  R-H-0805  [2012(0805)]
R127  3.3M  R-H-0805  [2012(0805)]
R128  10K  R-H-0805  [2012(0805)]
R129  10K  R-V-0805  [2012(0805)]
R130  100K  R-V-0805  [2012(0805)]
R131  1K  R-H-0805  [2012(0805)]
R132  80.6K  R-V-0805  [2012(0805)]
R133  200K  R-V-0805  [2012(0805)]
R134  1K  R-H-0805  [2012(0805)]
R135  200  R-H-0805  [2012(0805)]
R136  4.99K  R-V-0805  [2012(0805)]
R137  80.6K  R-H-0805  [2012(0805)]
R138  1K  R-V-0805  [2012(0805)]
R139  100  R-H-0805  [2012(0805)]
R140  10K  R-H-0805  [2012(0805)]
R141  200K  R-H-0805  [2012(0805)]
R142  3.3M  R-H-0805  [2012(0805)]
R143  10K  R-H-0805  [2012(0805)]
R144  10K  R-V-0805  [2012(0805)]
R145  100K  R-V-0805  [2012(0805)]
R146  1K  R-H-0805  [2012(0805)]
R147  80.6K  R-V-0805  [2012(0805)]
R148  200K  R-V-0805  [2012(0805)]
R149  1K  R-H-0805  [2012(0805)]
R150  200  R-H-0805  [2012(0805)]
R151  4.99K  R-V-0805  [2012(0805)]
R152  80.6K  R-H-0805  [2012(0805)]
R153  1K  R-V-0805  [2012(0805)]
R202  ???  R-H-0805  [2012(0805)]
R203  ???  R-H-0805  [2012(0805)]
R204  ???  R-H-0805  [2012(0805)]
R205  ???  R-H-0805  [2012(0805)]

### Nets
+5V: IC25.3(VCC1) IC29.3(VCC1) IC33.3(VCC1) IC37.3(VCC1) R97.2 R112.2 R127.2 R142.2 ; also sheet 1,2,4
+12V [Power]: C53.1 C60.1 C67.1 C74.1 IC26.8(PWR:V++) IC30.8(PWR:V++) IC34.8(PWR:V++) IC38.8(PWR:V++) R105.1 R120.1 R135.1 R150.1 ; also sheet 1,2,4
+12VA [Power]: C56.1 C63.1 C70.1 C77.1 IC24.8(PWR:V++) IC28.8(PWR:V++) IC32.8(PWR:V++) IC36.8(PWR:V++) ; also sheet 1,2,4
+12VB: IC23.3(VCC1) IC25.6(VCC2) IC27.3(VCC1) IC29.6(VCC2) IC31.3(VCC1) IC33.6(VCC2) IC35.3(VCC1) IC37.6(VCC2) ; also sheet 1,2,4
+15V [Power]: J21.1 J24.1 J27.1 J30.1 ; also sheet 1,2,4
-8V: IC23.5(I2) IC27.5(I2) IC31.5(I2) IC35.5(I2) ; also sheet 1,2,4
-15V [Power]: J21.2 J24.2 J27.2 J30.2 ; also sheet 1,2,4
AGND: C53.2 C55.1 C60.2 C62.1 C67.2 C69.1 C74.2 C76.1 D44.K(C) D45.K(C) D46.K(C) D47.K(C) IC26.3(A:+IN) IC26.4(PWR:V-) IC30.3(A:+IN) IC30.4(PWR:V-) IC34.3(A:+IN) IC34.4(PWR:V-) IC38.3(A:+IN) IC38.4(PWR:V-) J21.4 J24.4 J27.4 J30.4 R102.1 R106.1 R117.1 R121.1 R132.1 R136.1 R147.1 R151.1 ; also sheet 1,2,4
DRIVE: D20.3(C) D23.3(C) D26.3(C) D29.3(C) ; also sheet 1,2,4
GND: C56.2 C59.1 C63.2 C66.1 C70.2 C73.1 C77.2 C80.1 IC24.4(PWR:V-) IC28.4(PWR:V-) IC32.4(PWR:V-) IC36.4(PWR:V-) J19.SHIELD1 J19.SHIELD2 J20.SHIELD1 J20.SHIELD2 J22.SHIELD1 J22.SHIELD2 J23.SHIELD1 J23.SHIELD2 J25.SHIELD1 J25.SHIELD2 J26.SHIELD1 J26.SHIELD2 J28.SHIELD1 J28.SHIELD2 J29.SHIELD1 J29.SHIELD2 R99.1 R100.1 R103.1 R108.1 R114.1 R115.1 R118.1 R123.1 R129.1 R130.1 R133.1 R138.1 R144.1 R145.1 R148.1 R153.1 ; also sheet 1,2,4
N$120: J21.5 R94.1
N$121: D20.1(A) IC26.1(A:OUT) R94.2 R96.1
N$122: C54.1 IC26.2(A:-IN) R95.2 R97.1 R107.1 R202.2
N$123: C105.2 IC26.5(B:+IN) J21.3 R95.1
N$124: C54.2 R96.2
N$125: C57.2 IC23.2(LED+) IC24.1(A:OUT)
N$126: J20.CONDUCTOR R98.2
N$127: C59.2 IC24.3(A:+IN) R98.1 R99.2
N$128: C57.1 IC23.4(I1) IC24.2(A:-IN) R100.2
N$129: C58.2 IC26.7(B:OUT) R101.2
N$130: IC25.2(LED+) R101.1
N$131: C58.1 IC25.4(I1) IC26.6(B:-IN) R102.2
N$132: IC24.5(B:+IN) IC25.5(I2) R103.2
N$133: IC24.6(B:-IN) IC24.7(B:OUT) R104.1
N$134: J19.CONDUCTOR R104.2
N$135: D19.3(C) J21.6
N$136: J21.7 R105.2
N$137: D21.1(A) J21.8 R106.2
N$138: C55.2 IC23.6(VCC2) R107.2
N$139: IC23.1(LED-) R108.2
N$140: J24.5 R109.1
N$141: D23.1(A) IC30.1(A:OUT) R109.2 R111.1
N$142: C61.1 IC30.2(A:-IN) R110.2 R112.1 R122.1 R203.2
N$143: C106.2 IC30.5(B:+IN) J24.3 R110.1
N$144: C61.2 R111.2
N$145: C64.2 IC27.2(LED+) IC28.1(A:OUT)
N$146: J23.CONDUCTOR R113.2
N$147: C66.2 IC28.3(A:+IN) R113.1 R114.2
N$148: C64.1 IC27.4(I1) IC28.2(A:-IN) R115.2
N$149: C65.2 IC30.7(B:OUT) R116.2
N$150: IC29.2(LED+) R116.1
N$151: C65.1 IC29.4(I1) IC30.6(B:-IN) R117.2
N$152: IC28.5(B:+IN) IC29.5(I2) R118.2
N$153: IC28.6(B:-IN) IC28.7(B:OUT) R119.1
N$154: J22.CONDUCTOR R119.2
N$155: D22.3(C) J24.6
N$156: J24.7 R120.2
N$157: D24.1(A) J24.8 R121.2
N$158: C62.2 IC27.6(VCC2) R122.2
N$159: IC27.1(LED-) R123.2
N$160: J27.5 R124.1
N$161: D26.1(A) IC34.1(A:OUT) R124.2 R126.1
N$162: C68.1 IC34.2(A:-IN) R125.2 R127.1 R137.1 R205.2
N$163: C108.2 IC34.5(B:+IN) J27.3 R125.1
N$164: C68.2 R126.2
N$165: C71.2 IC31.2(LED+) IC32.1(A:OUT)
N$166: J26.CONDUCTOR R128.2
N$167: C73.2 IC32.3(A:+IN) R128.1 R129.2
N$168: C71.1 IC31.4(I1) IC32.2(A:-IN) R130.2
N$169: C72.2 IC34.7(B:OUT) R131.2
N$170: IC33.2(LED+) R131.1
N$171: C72.1 IC33.4(I1) IC34.6(B:-IN) R132.2
N$172: IC32.5(B:+IN) IC33.5(I2) R133.2
N$173: IC32.6(B:-IN) IC32.7(B:OUT) R134.1
N$174: J25.CONDUCTOR R134.2
N$175: D25.3(C) J27.6
N$176: J27.7 R135.2
N$177: D27.1(A) J27.8 R136.2
N$178: C69.2 IC31.6(VCC2) R137.2
N$179: IC31.1(LED-) R138.2
N$180: J30.5 R139.1
N$181: D29.1(A) IC38.1(A:OUT) R139.2 R141.1
N$182: C75.1 IC38.2(A:-IN) R140.2 R142.1 R152.1 R204.2
N$183: C107.2 IC38.5(B:+IN) J30.3 R140.1
N$184: C75.2 R141.2
N$185: C78.2 IC35.2(LED+) IC36.1(A:OUT)
N$186: J29.CONDUCTOR R143.2
N$187: C80.2 IC36.3(A:+IN) R143.1 R144.2
N$188: C78.1 IC35.4(I1) IC36.2(A:-IN) R145.2
N$189: C79.2 IC38.7(B:OUT) R146.2
N$190: IC37.2(LED+) R146.1
N$191: C79.1 IC37.4(I1) IC38.6(B:-IN) R147.2
N$192: IC36.5(B:+IN) IC37.5(I2) R148.2
N$193: IC36.6(B:-IN) IC36.7(B:OUT) R149.1
N$194: J28.CONDUCTOR R149.2
N$195: D28.3(C) J30.6
N$196: J30.7 R150.2
N$197: D30.1(A) J30.8 R151.2
N$198: C76.2 IC35.6(VCC2) R152.2
N$199: IC35.1(LED-) R153.2
N$263: C105.1 R202.1
N$264: C106.1 R203.1
N$265: C107.1 R204.1
N$266: C108.1 R205.1
N$274: D44.A IC25.1(LED-)
N$275: D45.A IC33.1(LED-)
N$276: D46.A IC37.1(LED-)
N$277: D47.A IC29.1(LED-)
TEMP: D21.3(C) D24.3(C) D27.3(C) D30.3(C) ; also sheet 1,2,4
V-DS: D19.1(A) D22.1(A) D25.1(A) D28.1(A) ; also sheet 1,2,4
Unconnected: J21.9 J24.9 J27.9 J30.9

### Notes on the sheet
- +Coil | +Coil
- Supply | Supply
- Coil #5 | Coil #6
- 6.8 Ohm | 6.8 Ohm
- Coil | Coil
- 2.2uF | 2.2uF
- See Notes | See Notes
- -15V | -15V
- Com | Com
- +15V | +15V
- Out | Out
- 10K | 10K
- (sic) | (sic)
- socket: | socket:
- (+4Vfs) | (+4Vfs)
- NTC 10K@25° | NTC 10K@25°
- +Coil | +Coil
- Supply | Supply
- Coil #7 | Coil #8
- 6.8 Ohm | 6.8 Ohm
- Coil | Coil
- 2.2uF | 2.2uF
- See Notes | See Notes
- -15V | -15V
- Com | Com
- +15V | +15V
- Out | Out
- 10K | 10K
- (sic) | (sic)
- socket: | socket:
- (+4Vfs) | (+4Vfs)
- NTC 10K@25° | NTC 10K@25°
- CATS2 Horizontal
- Cold Atoms Transfer System
- Control Input Side | Power Supplies Side
- Control Input Side | Power Supplies Side
- A1

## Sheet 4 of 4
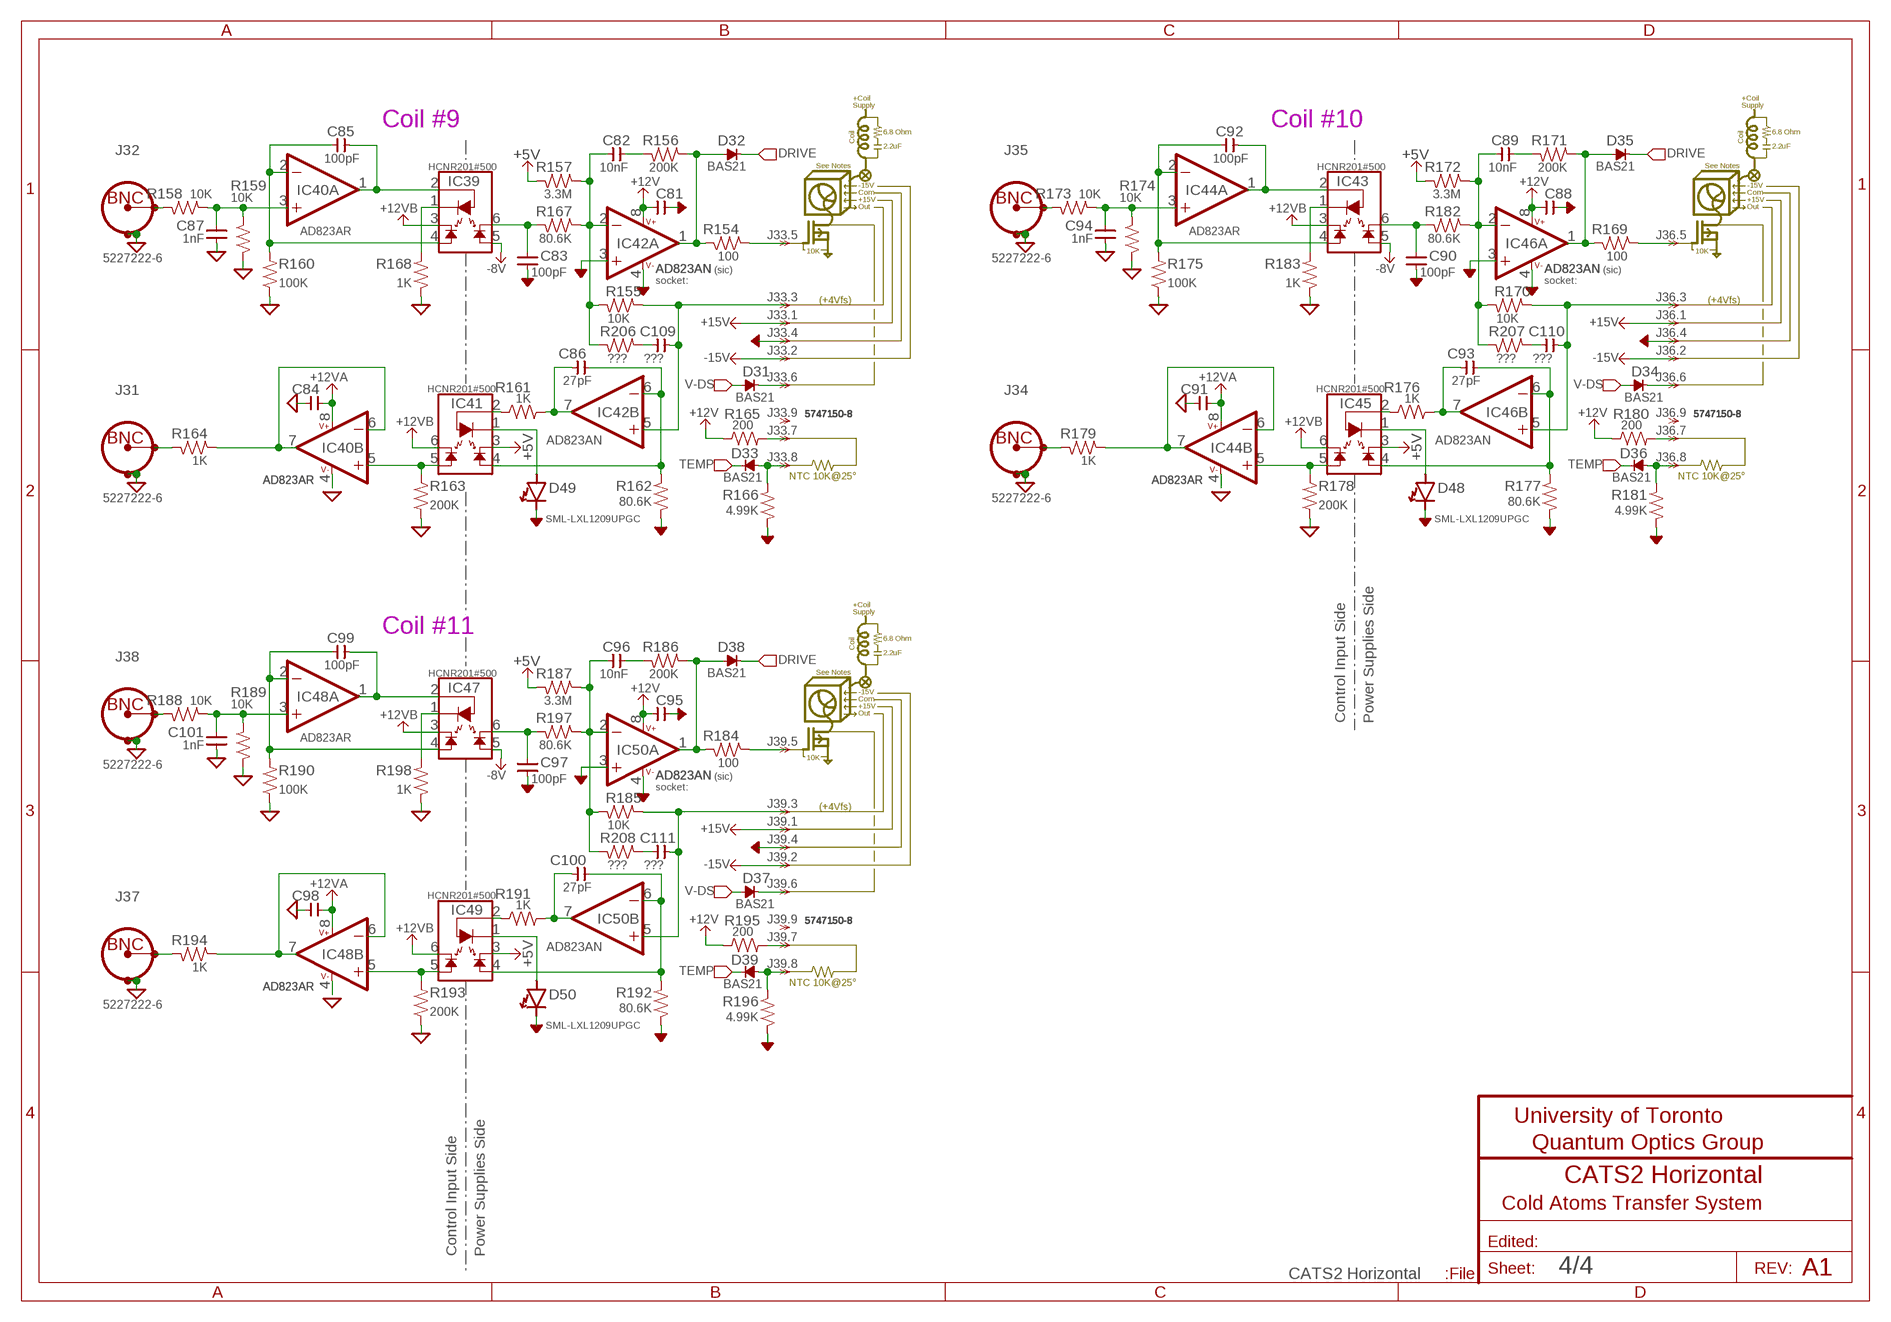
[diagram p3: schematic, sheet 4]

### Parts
C81  0.1uF  CAP-H-0805  [2012(0805)]
C82  10nF  CAP-H-0805  [2012(0805)]
C83  100pF  CAP-V-0805  [2012(0805)]
C84  0.1uF  CAP-H-0805  [2012(0805)]
C85  100pF  CAP-H-0805  [2012(0805)]
C86  27pF  CAP-H-0805  [2012(0805)]
C87  1nF  CAP-V-0805  [2012(0805)]
C88  0.1uF  CAP-H-0805  [2012(0805)]
C89  10nF  CAP-H-0805  [2012(0805)]
C90  100pF  CAP-V-0805  [2012(0805)]
C91  0.1uF  CAP-H-0805  [2012(0805)]
C92  100pF  CAP-H-0805  [2012(0805)]
C93  27pF  CAP-H-0805  [2012(0805)]
C94  1nF  CAP-V-0805  [2012(0805)]
C95  0.1uF  CAP-H-0805  [2012(0805)]
C96  10nF  CAP-H-0805  [2012(0805)]
C97  100pF  CAP-V-0805  [2012(0805)]
C98  0.1uF  CAP-H-0805  [2012(0805)]
C99  100pF  CAP-H-0805  [2012(0805)]
C100  27pF  CAP-H-0805  [2012(0805)]
C101  1nF  CAP-V-0805  [2012(0805)]
C109  ???  CAP-H-0805  [2012(0805)]
C110  ???  CAP-H-0805  [2012(0805)]
C111  ???  CAP-H-0805  [2012(0805)]
D31  BAS21  DIODE,GENERIC-SOT23  [SOT23]
D32  BAS21  DIODE,GENERIC-SOT23  [SOT23]
D33  BAS21  DIODE,GENERIC-SOT23  [SOT23]
D34  BAS21  DIODE,GENERIC-SOT23  [SOT23]
D35  BAS21  DIODE,GENERIC-SOT23  [SOT23]
D36  BAS21  DIODE,GENERIC-SOT23  [SOT23]
D37  BAS21  DIODE,GENERIC-SOT23  [SOT23]
D38  BAS21  DIODE,GENERIC-SOT23  [SOT23]
D39  BAS21  DIODE,GENERIC-SOT23  [SOT23]
D48  SML-LXL1209UPGC  LED-1209  [1209]
D49  SML-LXL1209UPGC  LED-1209  [1209]
D50  SML-LXL1209UPGC  LED-1209  [1209]
IC39  HCNR201#500  OPTO:LINEAR-TYPE1AVAGO#300  [SMD:AVAGO#300(8PIN)]
IC40  AD823AR  OPAMP:AD8___(DUAL)-SOIC-8  [SOIC-8]
IC41  HCNR201#500  OPTO:LINEAR-TYPE1AVAGO#300  [SMD:AVAGO#300(8PIN)]
IC42  AD823AN  OPAMP:AD8___(DUAL)-DIP8  [DIL08]
IC43  HCNR201#500  OPTO:LINEAR-TYPE1AVAGO#300  [SMD:AVAGO#300(8PIN)]
IC44  AD823AR  OPAMP:AD8___(DUAL)-SOIC-8  [SOIC-8]
IC45  HCNR201#500  OPTO:LINEAR-TYPE1AVAGO#300  [SMD:AVAGO#300(8PIN)]
IC46  AD823AN  OPAMP:AD8___(DUAL)-DIP8  [DIL08]
IC47  HCNR201#500  OPTO:LINEAR-TYPE1AVAGO#300  [SMD:AVAGO#300(8PIN)]
IC48  AD823AR  OPAMP:AD8___(DUAL)-SOIC-8  [SOIC-8]
IC49  HCNR201#500  OPTO:LINEAR-TYPE1AVAGO#300  [SMD:AVAGO#300(8PIN)]
IC50  AD823AN  OPAMP:AD8___(DUAL)-DIP8  [DIL08]
J31  5227222-6  CONN-BNC-TYPE1VERT  [CONN-BNC-AMP-TYPE1VERT]
J32  5227222-6  CONN-BNC-TYPE1VERT  [CONN-BNC-AMP-TYPE1VERT]
J33  5747150-8  CONN-DB9-TYPE2-AMP_5747XXX  [CONN-DB9-H/V1]
J34  5227222-6  CONN-BNC-TYPE1VERT  [CONN-BNC-AMP-TYPE1VERT]
J35  5227222-6  CONN-BNC-TYPE1VERT  [CONN-BNC-AMP-TYPE1VERT]
J36  5747150-8  CONN-DB9-TYPE2-AMP_5747XXX  [CONN-DB9-H/V1]
J37  5227222-6  CONN-BNC-TYPE1VERT  [CONN-BNC-AMP-TYPE1VERT]
J38  5227222-6  CONN-BNC-TYPE1VERT  [CONN-BNC-AMP-TYPE1VERT]
J39  5747150-8  CONN-DB9-TYPE2-AMP_5747XXX  [CONN-DB9-H/V1]
R154  100  R-H-0805  [2012(0805)]
R155  10K  R-H-0805  [2012(0805)]
R156  200K  R-H-0805  [2012(0805)]
R157  3.3M  R-H-0805  [2012(0805)]
R158  10K  R-H-0805  [2012(0805)]
R159  10K  R-V-0805  [2012(0805)]
R160  100K  R-V-0805  [2012(0805)]
R161  1K  R-H-0805  [2012(0805)]
R162  80.6K  R-V-0805  [2012(0805)]
R163  200K  R-V-0805  [2012(0805)]
R164  1K  R-H-0805  [2012(0805)]
R165  200  R-H-0805  [2012(0805)]
R166  4.99K  R-V-0805  [2012(0805)]
R167  80.6K  R-H-0805  [2012(0805)]
R168  1K  R-V-0805  [2012(0805)]
R169  100  R-H-0805  [2012(0805)]
R170  10K  R-H-0805  [2012(0805)]
R171  200K  R-H-0805  [2012(0805)]
R172  3.3M  R-H-0805  [2012(0805)]
R173  10K  R-H-0805  [2012(0805)]
R174  10K  R-V-0805  [2012(0805)]
R175  100K  R-V-0805  [2012(0805)]
R176  1K  R-H-0805  [2012(0805)]
R177  80.6K  R-V-0805  [2012(0805)]
R178  200K  R-V-0805  [2012(0805)]
R179  1K  R-H-0805  [2012(0805)]
R180  200  R-H-0805  [2012(0805)]
R181  4.99K  R-V-0805  [2012(0805)]
R182  80.6K  R-H-0805  [2012(0805)]
R183  1K  R-V-0805  [2012(0805)]
R184  100  R-H-0805  [2012(0805)]
R185  10K  R-H-0805  [2012(0805)]
R186  200K  R-H-0805  [2012(0805)]
R187  3.3M  R-H-0805  [2012(0805)]
R188  10K  R-H-0805  [2012(0805)]
R189  10K  R-V-0805  [2012(0805)]
R190  100K  R-V-0805  [2012(0805)]
R191  1K  R-H-0805  [2012(0805)]
R192  80.6K  R-V-0805  [2012(0805)]
R193  200K  R-V-0805  [2012(0805)]
R194  1K  R-H-0805  [2012(0805)]
R195  200  R-H-0805  [2012(0805)]
R196  4.99K  R-V-0805  [2012(0805)]
R197  80.6K  R-H-0805  [2012(0805)]
R198  1K  R-V-0805  [2012(0805)]
R206  ???  R-H-0805  [2012(0805)]
R207  ???  R-H-0805  [2012(0805)]
R208  ???  R-H-0805  [2012(0805)]

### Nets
+5V: IC41.3(VCC1) IC45.3(VCC1) IC49.3(VCC1) R157.2 R172.2 R187.2 ; also sheet 1,2,3
+12V [Power]: C81.1 C88.1 C95.1 IC42.8(PWR:V++) IC46.8(PWR:V++) IC50.8(PWR:V++) R165.1 R180.1 R195.1 ; also sheet 1,2,3
+12VA [Power]: C84.1 C91.1 C98.1 IC40.8(PWR:V++) IC44.8(PWR:V++) IC48.8(PWR:V++) ; also sheet 1,2,3
+12VB: IC39.3(VCC1) IC41.6(VCC2) IC43.3(VCC1) IC45.6(VCC2) IC47.3(VCC1) IC49.6(VCC2) ; also sheet 1,2,3
+15V [Power]: J33.1 J36.1 J39.1 ; also sheet 1,2,3
-8V: IC39.5(I2) IC43.5(I2) IC47.5(I2) ; also sheet 1,2,3
-15V [Power]: J33.2 J36.2 J39.2 ; also sheet 1,2,3
AGND: C81.2 C83.1 C88.2 C90.1 C95.2 C97.1 D48.K(C) D49.K(C) D50.K(C) IC42.3(A:+IN) IC42.4(PWR:V-) IC46.3(A:+IN) IC46.4(PWR:V-) IC50.3(A:+IN) IC50.4(PWR:V-) J33.4 J36.4 J39.4 R162.1 R166.1 R177.1 R181.1 R192.1 R196.1 ; also sheet 1,2,3
DRIVE: D32.3(C) D35.3(C) D38.3(C) ; also sheet 1,2,3
GND: C84.2 C87.1 C91.2 C94.1 C98.2 C101.1 IC40.4(PWR:V-) IC44.4(PWR:V-) IC48.4(PWR:V-) J31.SHIELD1 J31.SHIELD2 J32.SHIELD1 J32.SHIELD2 J34.SHIELD1 J34.SHIELD2 J35.SHIELD1 J35.SHIELD2 J37.SHIELD1 J37.SHIELD2 J38.SHIELD1 J38.SHIELD2 R159.1 R160.1 R163.1 R168.1 R174.1 R175.1 R178.1 R183.1 R189.1 R190.1 R193.1 R198.1 ; also sheet 1,2,3
N$200: J33.5 R154.1
N$201: D32.1(A) IC42.1(A:OUT) R154.2 R156.1
N$202: C82.1 IC42.2(A:-IN) R155.2 R157.1 R167.1 R206.2
N$203: C109.2 IC42.5(B:+IN) J33.3 R155.1
N$204: C82.2 R156.2
N$205: C85.2 IC39.2(LED+) IC40.1(A:OUT)
N$206: J32.CONDUCTOR R158.2
N$207: C87.2 IC40.3(A:+IN) R158.1 R159.2
N$208: C85.1 IC39.4(I1) IC40.2(A:-IN) R160.2
N$209: C86.2 IC42.7(B:OUT) R161.2
N$210: IC41.2(LED+) R161.1
N$211: C86.1 IC41.4(I1) IC42.6(B:-IN) R162.2
N$212: IC40.5(B:+IN) IC41.5(I2) R163.2
N$213: IC40.6(B:-IN) IC40.7(B:OUT) R164.1
N$214: J31.CONDUCTOR R164.2
N$215: D31.3(C) J33.6
N$216: J33.7 R165.2
N$217: D33.1(A) J33.8 R166.2
N$218: C83.2 IC39.6(VCC2) R167.2
N$219: IC39.1(LED-) R168.2
N$220: J36.5 R169.1
N$221: D35.1(A) IC46.1(A:OUT) R169.2 R171.1
N$222: C89.1 IC46.2(A:-IN) R170.2 R172.1 R182.1 R207.2
N$223: C110.2 IC46.5(B:+IN) J36.3 R170.1
N$224: C89.2 R171.2
N$225: C92.2 IC43.2(LED+) IC44.1(A:OUT)
N$226: J35.CONDUCTOR R173.2
N$227: C94.2 IC44.3(A:+IN) R173.1 R174.2
N$228: C92.1 IC43.4(I1) IC44.2(A:-IN) R175.2
N$229: C93.2 IC46.7(B:OUT) R176.2
N$230: IC45.2(LED+) R176.1
N$231: C93.1 IC45.4(I1) IC46.6(B:-IN) R177.2
N$232: IC44.5(B:+IN) IC45.5(I2) R178.2
N$233: IC44.6(B:-IN) IC44.7(B:OUT) R179.1
N$234: J34.CONDUCTOR R179.2
N$235: D34.3(C) J36.6
N$236: J36.7 R180.2
N$237: D36.1(A) J36.8 R181.2
N$238: C90.2 IC43.6(VCC2) R182.2
N$239: IC43.1(LED-) R183.2
N$240: J39.5 R184.1
N$241: D38.1(A) IC50.1(A:OUT) R184.2 R186.1
N$242: C96.1 IC50.2(A:-IN) R185.2 R187.1 R197.1 R208.2
N$243: C111.2 IC50.5(B:+IN) J39.3 R185.1
N$244: C96.2 R186.2
N$245: C99.2 IC47.2(LED+) IC48.1(A:OUT)
N$246: J38.CONDUCTOR R188.2
N$247: C101.2 IC48.3(A:+IN) R188.1 R189.2
N$248: C99.1 IC47.4(I1) IC48.2(A:-IN) R190.2
N$249: C100.2 IC50.7(B:OUT) R191.2
N$250: IC49.2(LED+) R191.1
N$251: C100.1 IC49.4(I1) IC50.6(B:-IN) R192.2
N$252: IC48.5(B:+IN) IC49.5(I2) R193.2
N$253: IC48.6(B:-IN) IC48.7(B:OUT) R194.1
N$254: J37.CONDUCTOR R194.2
N$255: D37.3(C) J39.6
N$256: J39.7 R195.2
N$257: D39.1(A) J39.8 R196.2
N$258: C97.2 IC47.6(VCC2) R197.2
N$259: IC47.1(LED-) R198.2
N$268: C109.1 R206.1
N$269: C110.1 R207.1
N$270: C111.1 R208.1
N$278: D48.A IC45.1(LED-)
N$279: D49.A IC41.1(LED-)
N$280: D50.A IC49.1(LED-)
TEMP: D33.3(C) D36.3(C) D39.3(C) ; also sheet 1,2,3
V-DS: D31.1(A) D34.1(A) D37.1(A) ; also sheet 1,2,3
Unconnected: J33.9 J36.9 J39.9

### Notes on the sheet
- +Coil | +Coil
- Supply | Supply
- Coil #9 | Coil #10
- 6.8 Ohm | 6.8 Ohm
- Coil | Coil
- 2.2uF | 2.2uF
- See Notes | See Notes
- -15V | -15V
- Com | Com
- +15V | +15V
- Out | Out
- 10K | 10K
- (sic) | (sic)
- socket: | socket:
- (+4Vfs) | (+4Vfs)
- NTC 10K@25° | NTC 10K@25°
- +Coil
- Supply
- Coil #11
- 6.8 Ohm
- Coil
- 2.2uF
- See Notes
- -15V
- Com
- +15V
- Out
- Control Input Side | Power Supplies Side
- 10K
- (sic)
- socket:
- (+4Vfs)
- NTC 10K@25°
- CATS2 Horizontal
- Cold Atoms Transfer System
- Control Input Side | Power Supplies Side
- A1

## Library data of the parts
AUD1 AUD2 = QuantumOptics:AUDIO_DEVICE1: Audio Warning Device, Mallory MSR series, through hole, various sounds.
C1 C5 C10 C13 C14 C19 C24 C27 C32 C35 C41 C45 C48 C52 C55 C59 C62 C66 C69 C73 C76 C80 C83 C87 C90 C94 C97 C101 = QuantumOptics:CAP-V-: Cap, SMT and Through-hole, 0402 and up.
C2 C4 C7-C9 C11 C12 C16-C18 C23 C25 C26 C28-C31 C33 C34 C36-C40 C42-C44 C46 C47 C49-C51 C53 C54 C56-C58 C60 C61 C63-C65 C67 C68 C70-C72 C74 C75 C77-C79 C81 C82 C84-C86 C88 C89 C91-C93 C95 C96 C98-C100 C102-C111 = QuantumOptics:CAP-H-: Cap, SMT and Through-hole, 0402 and up.
C3 C6 C15 C20-C22 = QuantumOptics:CAP-POL-: Capacitor, Polarized, SMT 0805 and up, probably tantalum.
D1 D7-D39 = QuantumOptics:DIODE,GENERIC: Diode, Generic, plain old vanilla diodes.
D2-D6 = QuantumOptics:ZENER: Zener
D40-D50 = QuantumOptics:LED: LED
F1 = QuantumOptics:FUSE: Fuse
IC1 = QuantumOptics:OPAMP: Op Amp, generic, pick the right package. e.g. AD8605: SOT-23-5, RRIO, 10MHz, Ib = 1pA, Vio < 65uV, 2.7-5.5V.
IC2 IC8 IC9 IC12 IC13 IC15 IC17 IC19 IC21 IC23 IC25 IC27 IC29 IC31 IC33 IC35 IC37 IC39 IC41 IC43 IC45 IC47 IC49 = QuantumOptics:OPTO:LINEAR-TYPE1: Linear opto-coupler, Avago HCNR20x or Clare LOC11x Best: http://www.avagotech.com/docs/AV02-0886EN Okay: http://www.clare.com/home/pdfs.nsf/www/LOC110.pdf/$file/LOC110.pdf
IC3 IC6 IC10 IC11 IC14 IC16 IC18 IC20 IC22 IC24 IC26 IC28 IC30 IC32 IC34 IC36 IC38 IC40 IC42 IC44 IC46 IC48 IC50 = QuantumOptics:OPAMP:AD8___(DUAL): AD8xxx, Analog Devices, dual opamp in SOIC-8 and MSOP-8, various versions available. AD8066, AD8656, etc. e.g. http://www.analog.com/UploadedFiles/Data_Sheets/476080131AD8655_6_a.pdf
IC4 = QuantumOptics:LOGIC,MONOSTABLE,DUAL:MC74HC4538A: Monostable Multivibrator, dual, 74CH or CD4000 families, ON Semi or TI or Fairchild, xx4538 variant only, different pinout for xx14538. http://www.onsemi.com/PowerSolutions/product.do?id=MC74HC4538ADG, http://www.fairchildsemi.com/ds/CD%2FCD4538BC.pdf
IC5 = QuantumOptics:REGULATOR:LT3080(3PIN,LDO,I-SET): LT3080, LDO, output set by single resistor, nice part, LinTech, 1A, SOT223, MSOP8, TO220. http://cds.linear.com/docs/Datasheet/3080f.pdf
IC7 = QuantumOptics:OPTO:6N136: 6N136 optocoupler, Fairchild et al, 1Mbps CTR=27%typ, http://www.fairchildsemi.com/ds/6N/6N136.pdf, Can drop-in 6N137 with 10Mbps logic - http://www.fairchildsemi.com/ds/6N/6N137.pdf
J1 J2 J5-J8 J10 J11 J13 J14 J16 J17 J19 J20 J22 J23 J25 J26 J28 J29 J31 J32 J34 J35 J37 J38 = QuantumOptics:CONN-BNC: BNC PCB, horizontal or vertical, e.g. Horiz: Amp (5)227677-1, nut 1-329631-2, shoulder washer 330620. The two shield connections allow the assembly on either side of the board. Vert isolated: 5227222-6, http://catalog.tycoelectronics.com/TE/bin/TE.Connect?C=1&M=BYPN&TCPN=5227222-6&RQPN=5227222-6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; DESC: Input?
J3 = QuantumOptics:JUMPER-1X2: Jumper, header, SIP on 0.1" grid, for option selection.
J4 J9 J12 J15 J18 J21 J24 J27 J30 J33 J36 J39 = QuantumOptics:CONN-DB9-TYPE2: Connector, DB9, board mount, e.g. Tyco 1-5747150-4.
PWR1 PWR2 = QuantumOptics:DC-DC:CCP-__-E(TDK1.5-25W): CCp-inoutsc-E, TDK DC-DC isolated, 1.5-25W, uni- or bipolar "p": 1.5, 3, 6, 10, 15, or 25W. "in": Input 05, 12, 24 or 48V. "out": Output 3.3, 5, 12, ±12 (or 24), ±15 (or30V). "s": Polarity single or dual. "c": Case horiz DIP, horiz SMD or vertical SIP. http://www.tdk.co.jp/tefe02/ea335_cc_e.pdf
Q1 Q3 Q4 Q6 = QuantumOptics:BJT-NPN: NPN BJT, generic, p/n defined by VALUE field. E.g. Fairchild MMBT5551 (abs max 160V, 600mA. hFE>80@10mA.
Q2 Q5 = QuantumOptics:MOSFET-N: Mosfet, N-Channel, generic enhancement mode N-FET.
R1 R4 R7 R10-R12 R21-R23 R25 R30-R33 R38-R43 R46 R47 R49 R50 R55-R59 R61 R62 R64-R68 R71 R74 R75 R77 R79-R83 R86 R89 R90 R92 R94-R98 R101 R104 R105 R107 R109-R113 R116 R119 R120 R122 R124-R128 R131 R134 R135 R137 R139-R143 R146 R149 R150 R152 R154-R158 R161 R164 R165 R167 R169-R173 R176 R179 R180 R182 R184-R188 R191 R194 R195 R197 R200-R208 = QuantumOptics:R-H-*: Resistor, SMT & Through-Hole, horizontal symbol
R2 R3 R5 R8 R9 R13-R20 R24 R26-R29 R34-R37 R44 R48 R51-R54 R60 R63 R69 R70 R72 R73 R76 R78 R84 R85 R87 R88 R91 R93 R99 R100 R102 R103 R106 R108 R114 R115 R117 R118 R121 R123 R129 R130 R132 R133 R136 R138 R144 R145 R147 R148 R151 R153 R159 R160 R162 R163 R166 R168 R174 R175 R177 R178 R181 R183 R189 R190 R192 R193 R196 R198 = QuantumOptics:R-V-*: Resistor, SMT & Through-Hole, vertical symbol
R6 R45 R199 = QuantumOptics:POT: Pot, regular or trimpot
RLY1 = QuantumOptics:RELAY:SPDT: SPDT Relay
TP = QuantumOptics:CONN-TP2: Terminal Block, 2 post, generic two post terminal block.

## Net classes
1 Power: width 0.381 mm, drill 0.711 mm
